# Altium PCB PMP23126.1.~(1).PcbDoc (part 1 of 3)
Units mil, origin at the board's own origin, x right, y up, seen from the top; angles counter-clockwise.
Board outline 1315.03 x 1390.8 mil, 6 copper layers (Top Layer, MidLayer1, MidLayer2, MidLayer3, MidLayer4, Bottom Layer), stack 78 mil thick; 49 components, 55 nets, 222 pads, 193 vias.
Unrouted connection lines stored in the file: 15.
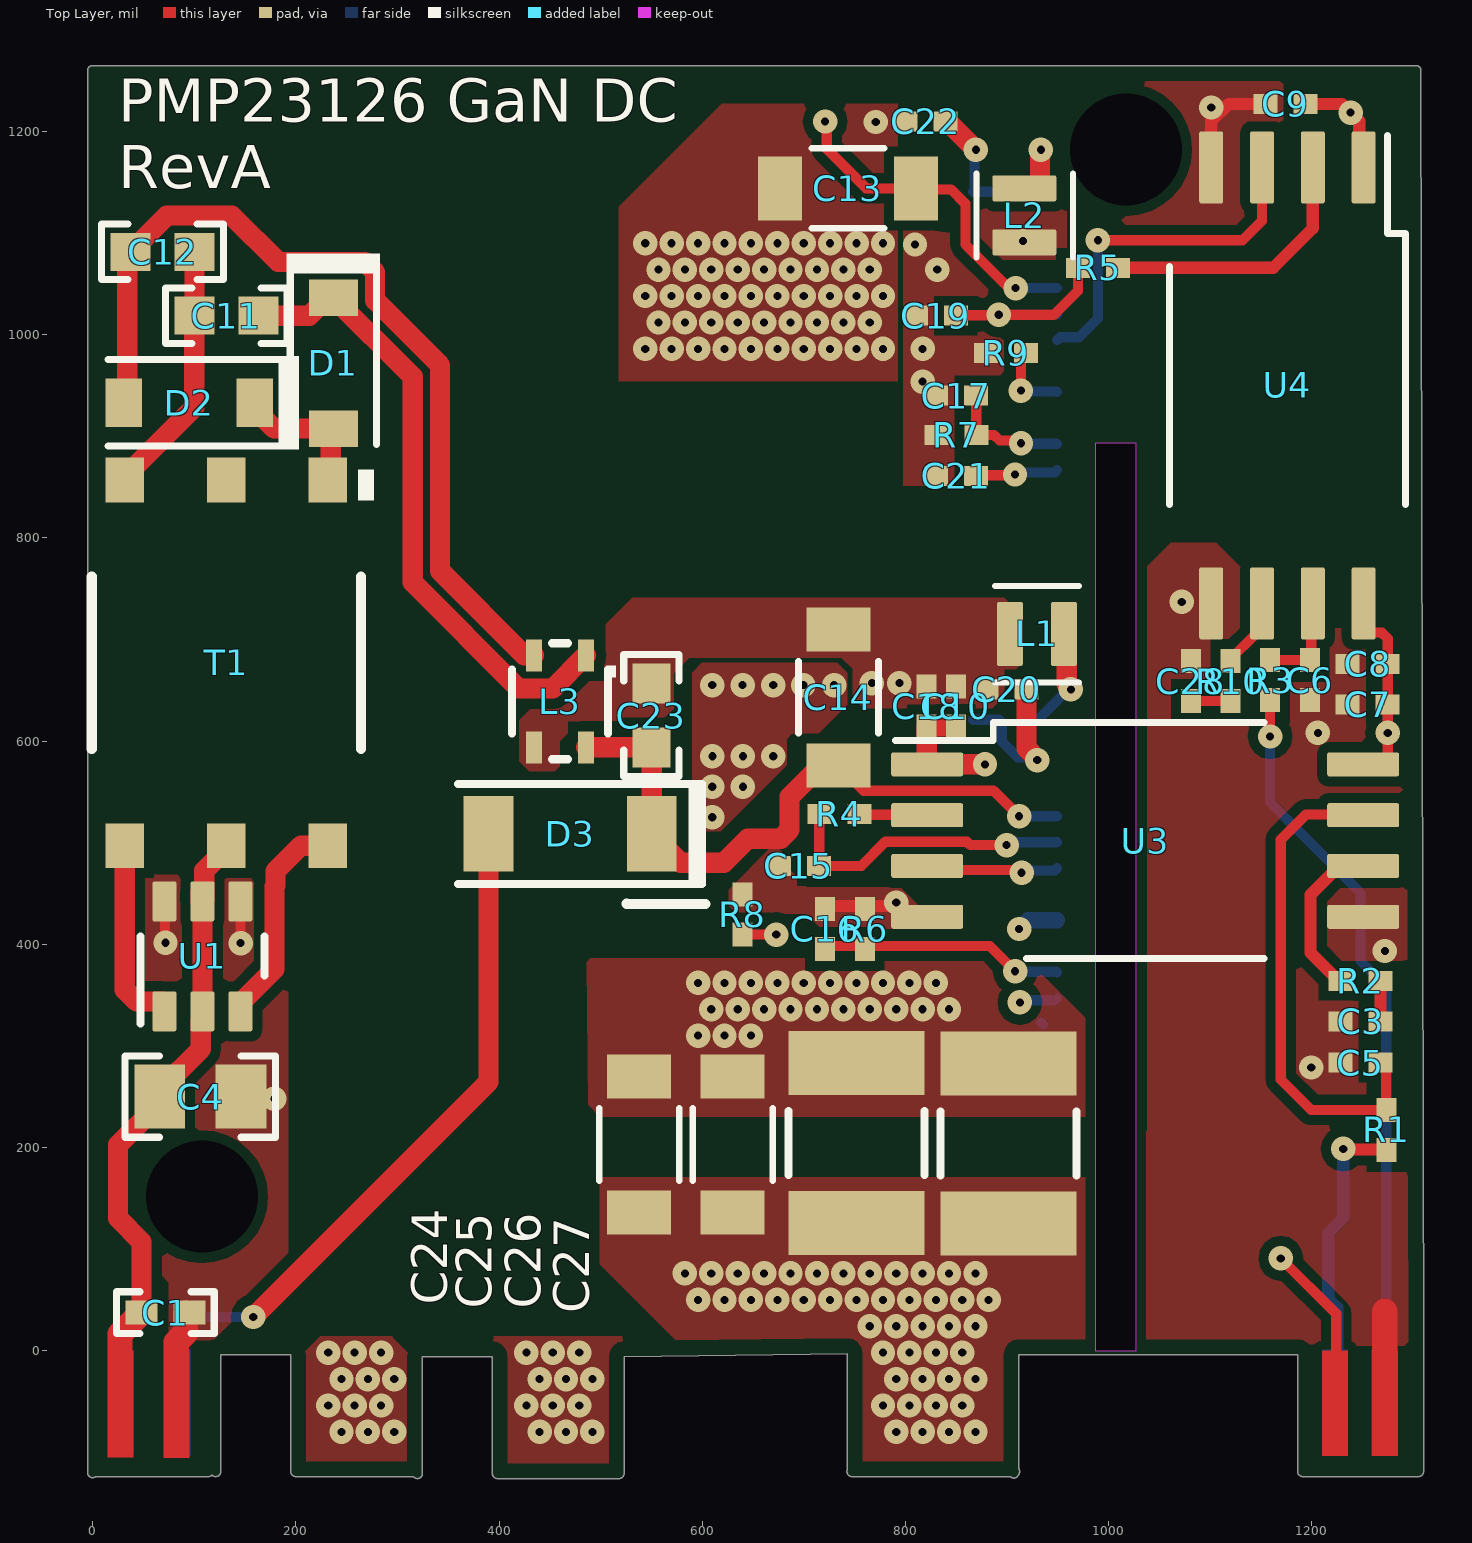
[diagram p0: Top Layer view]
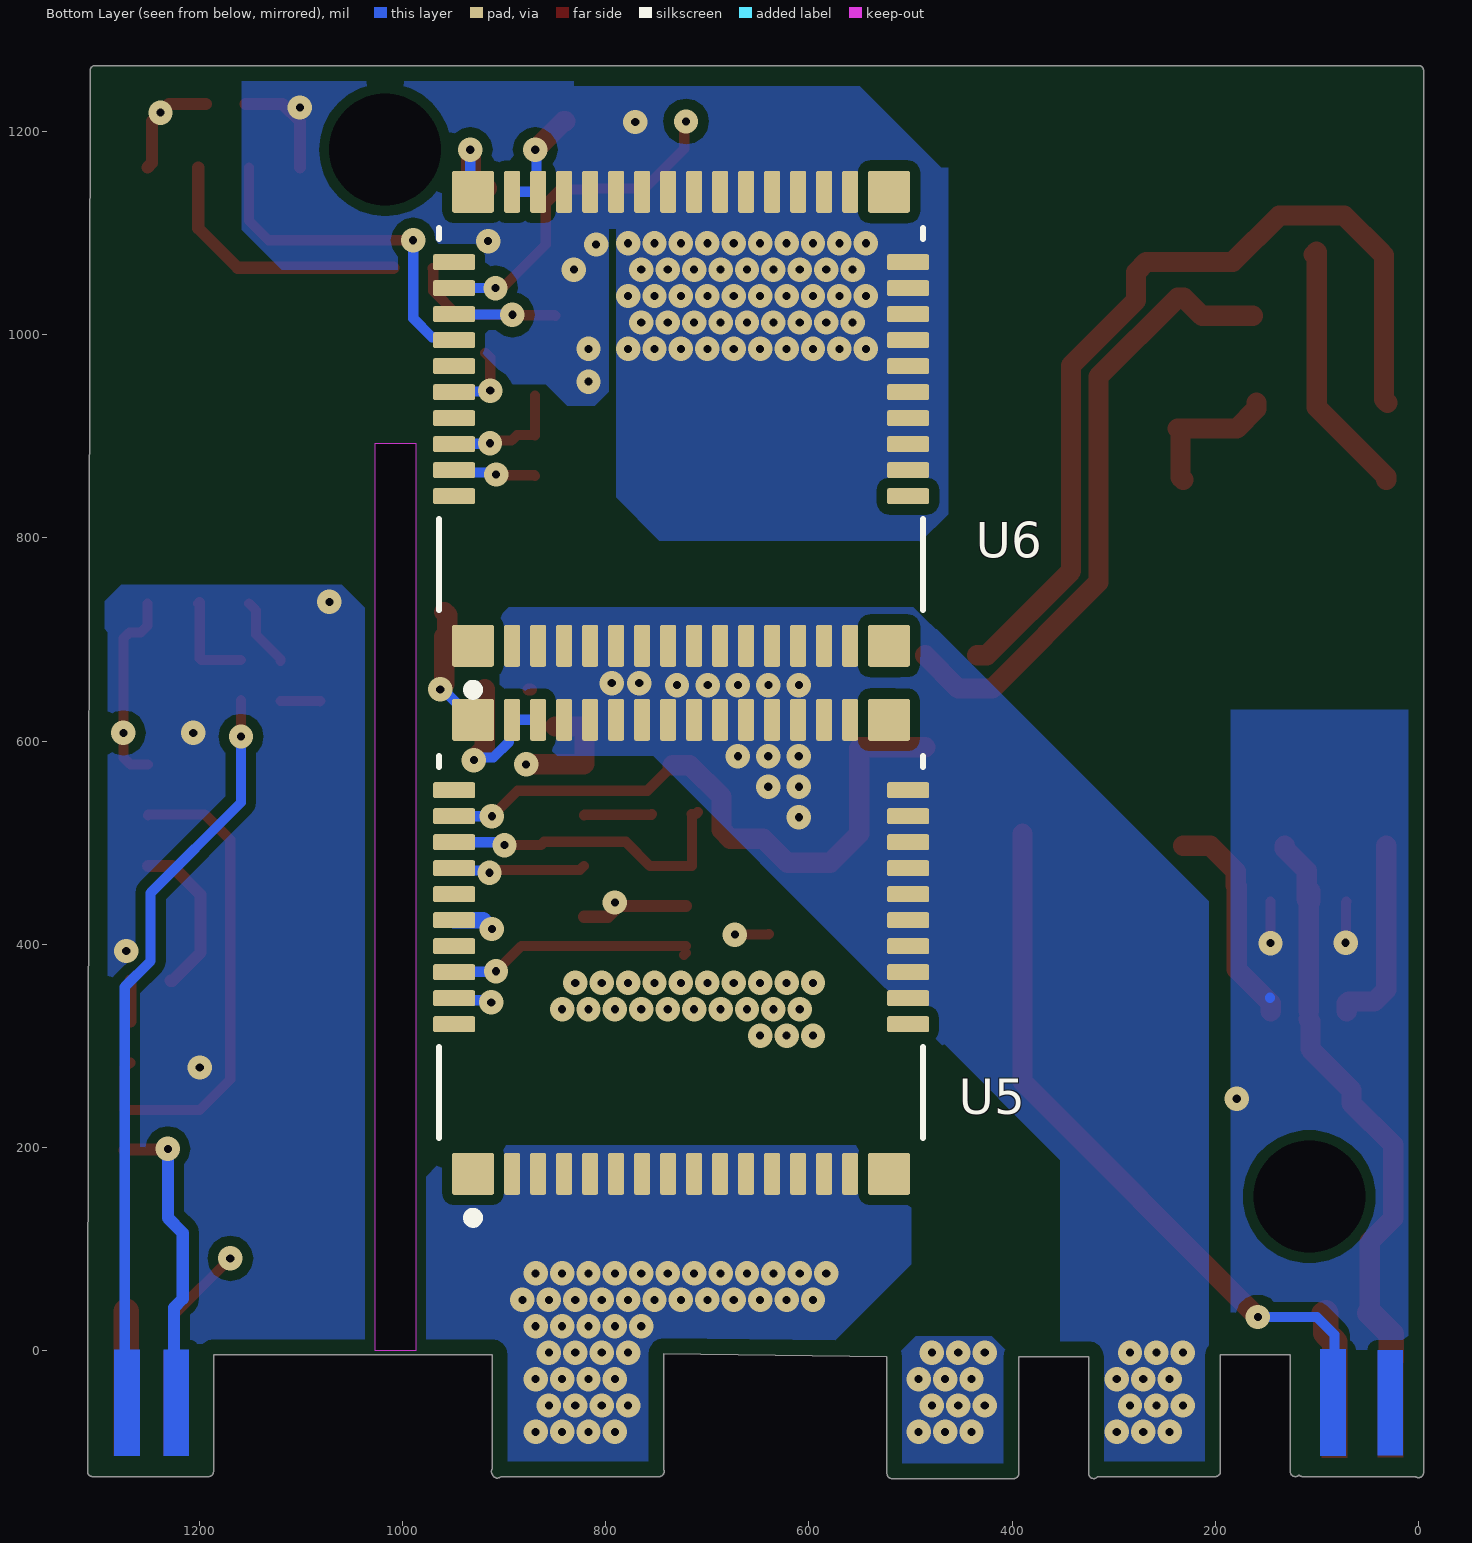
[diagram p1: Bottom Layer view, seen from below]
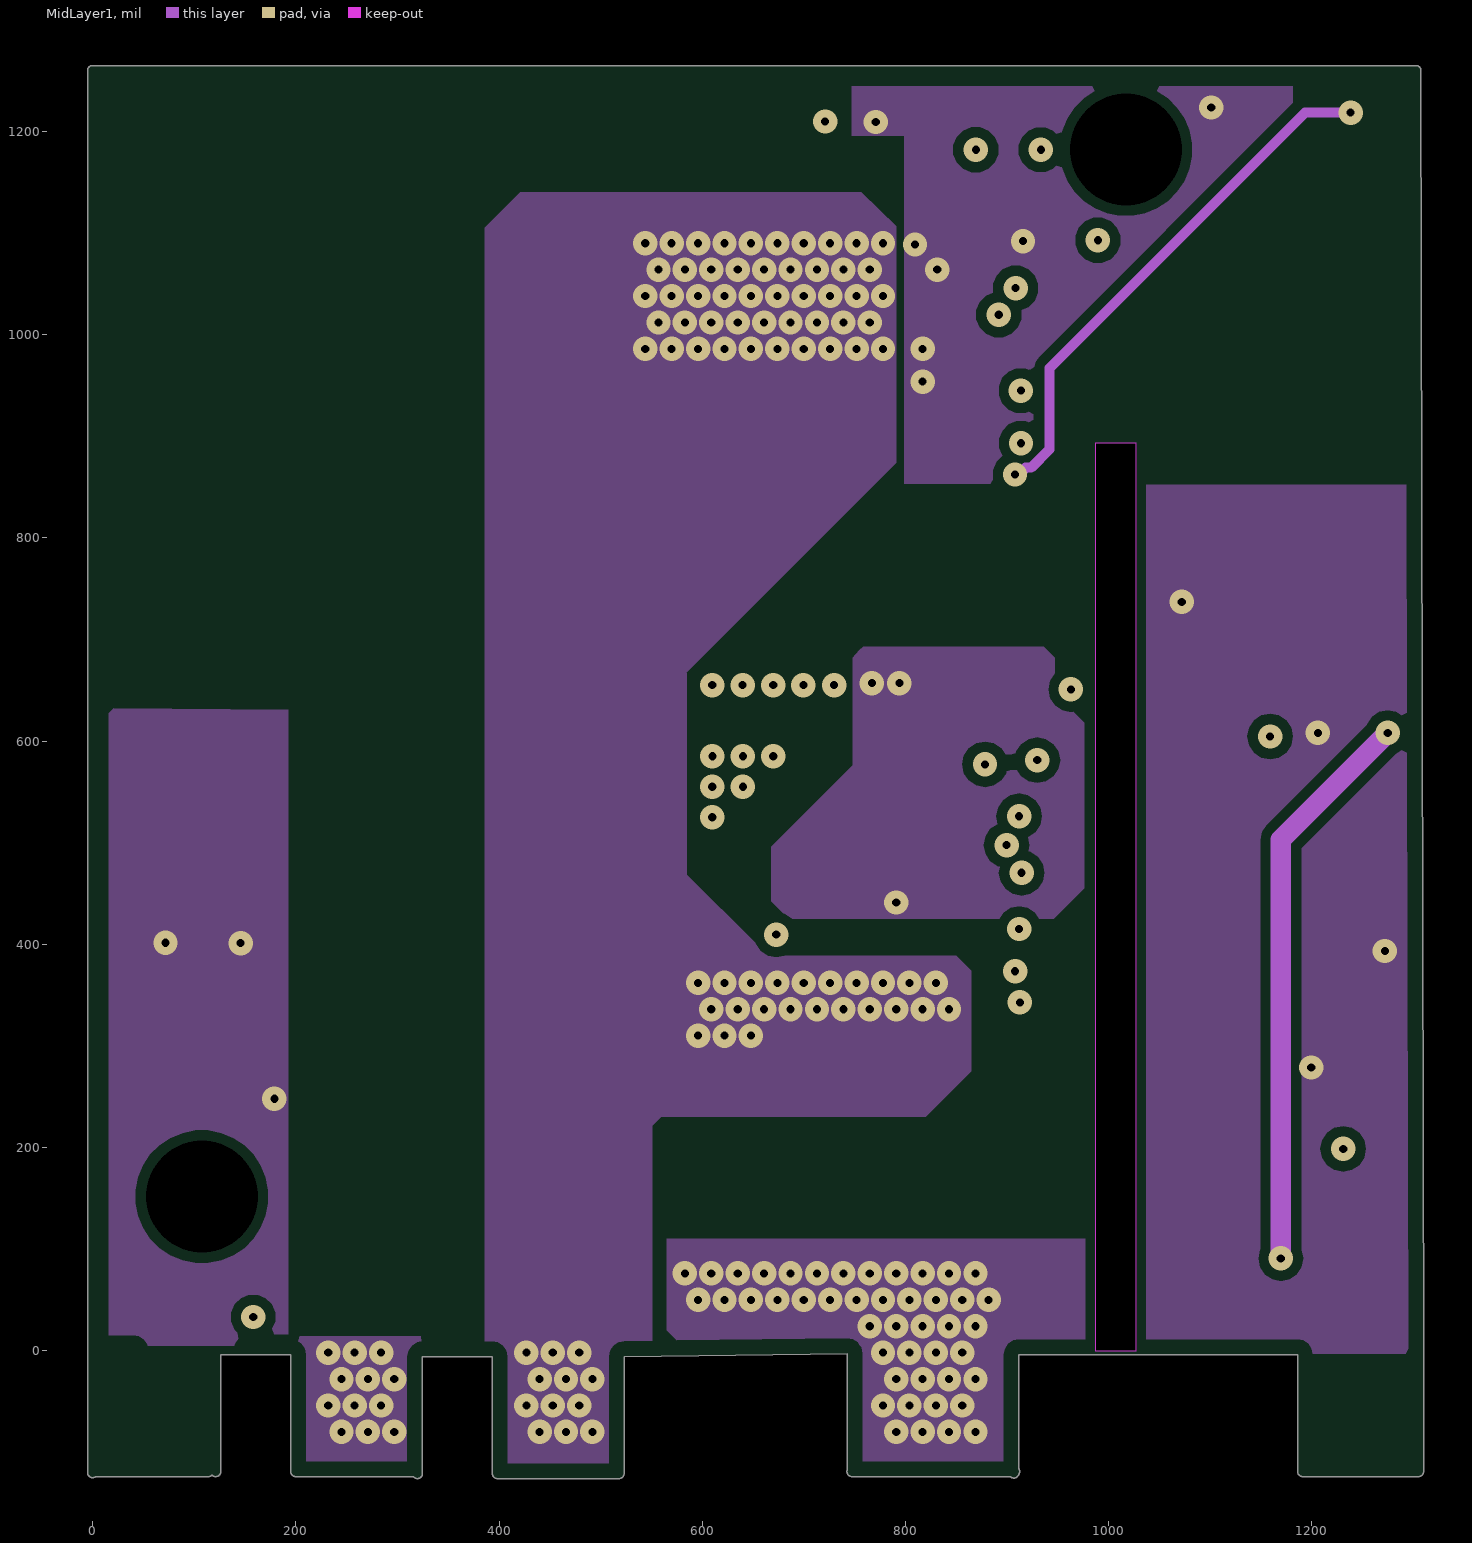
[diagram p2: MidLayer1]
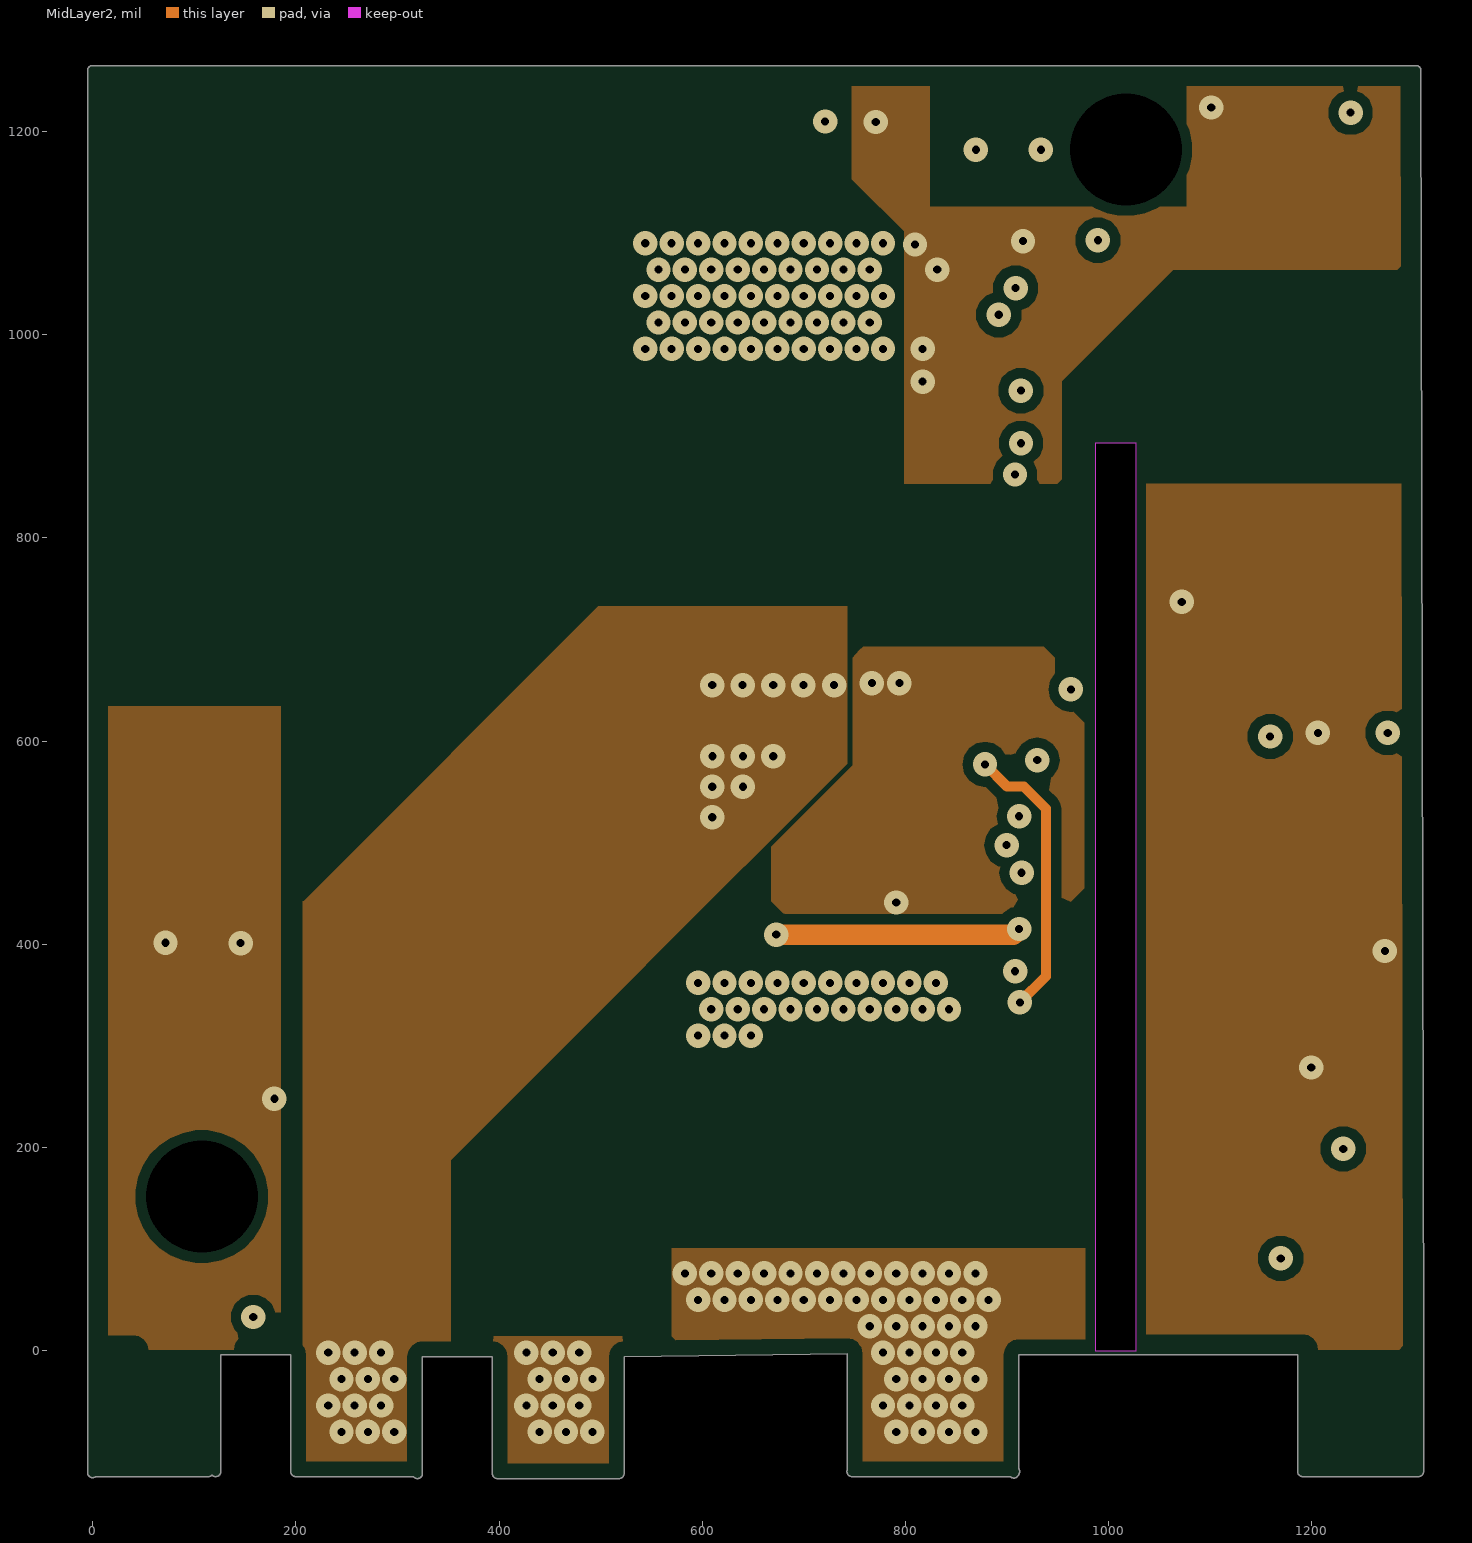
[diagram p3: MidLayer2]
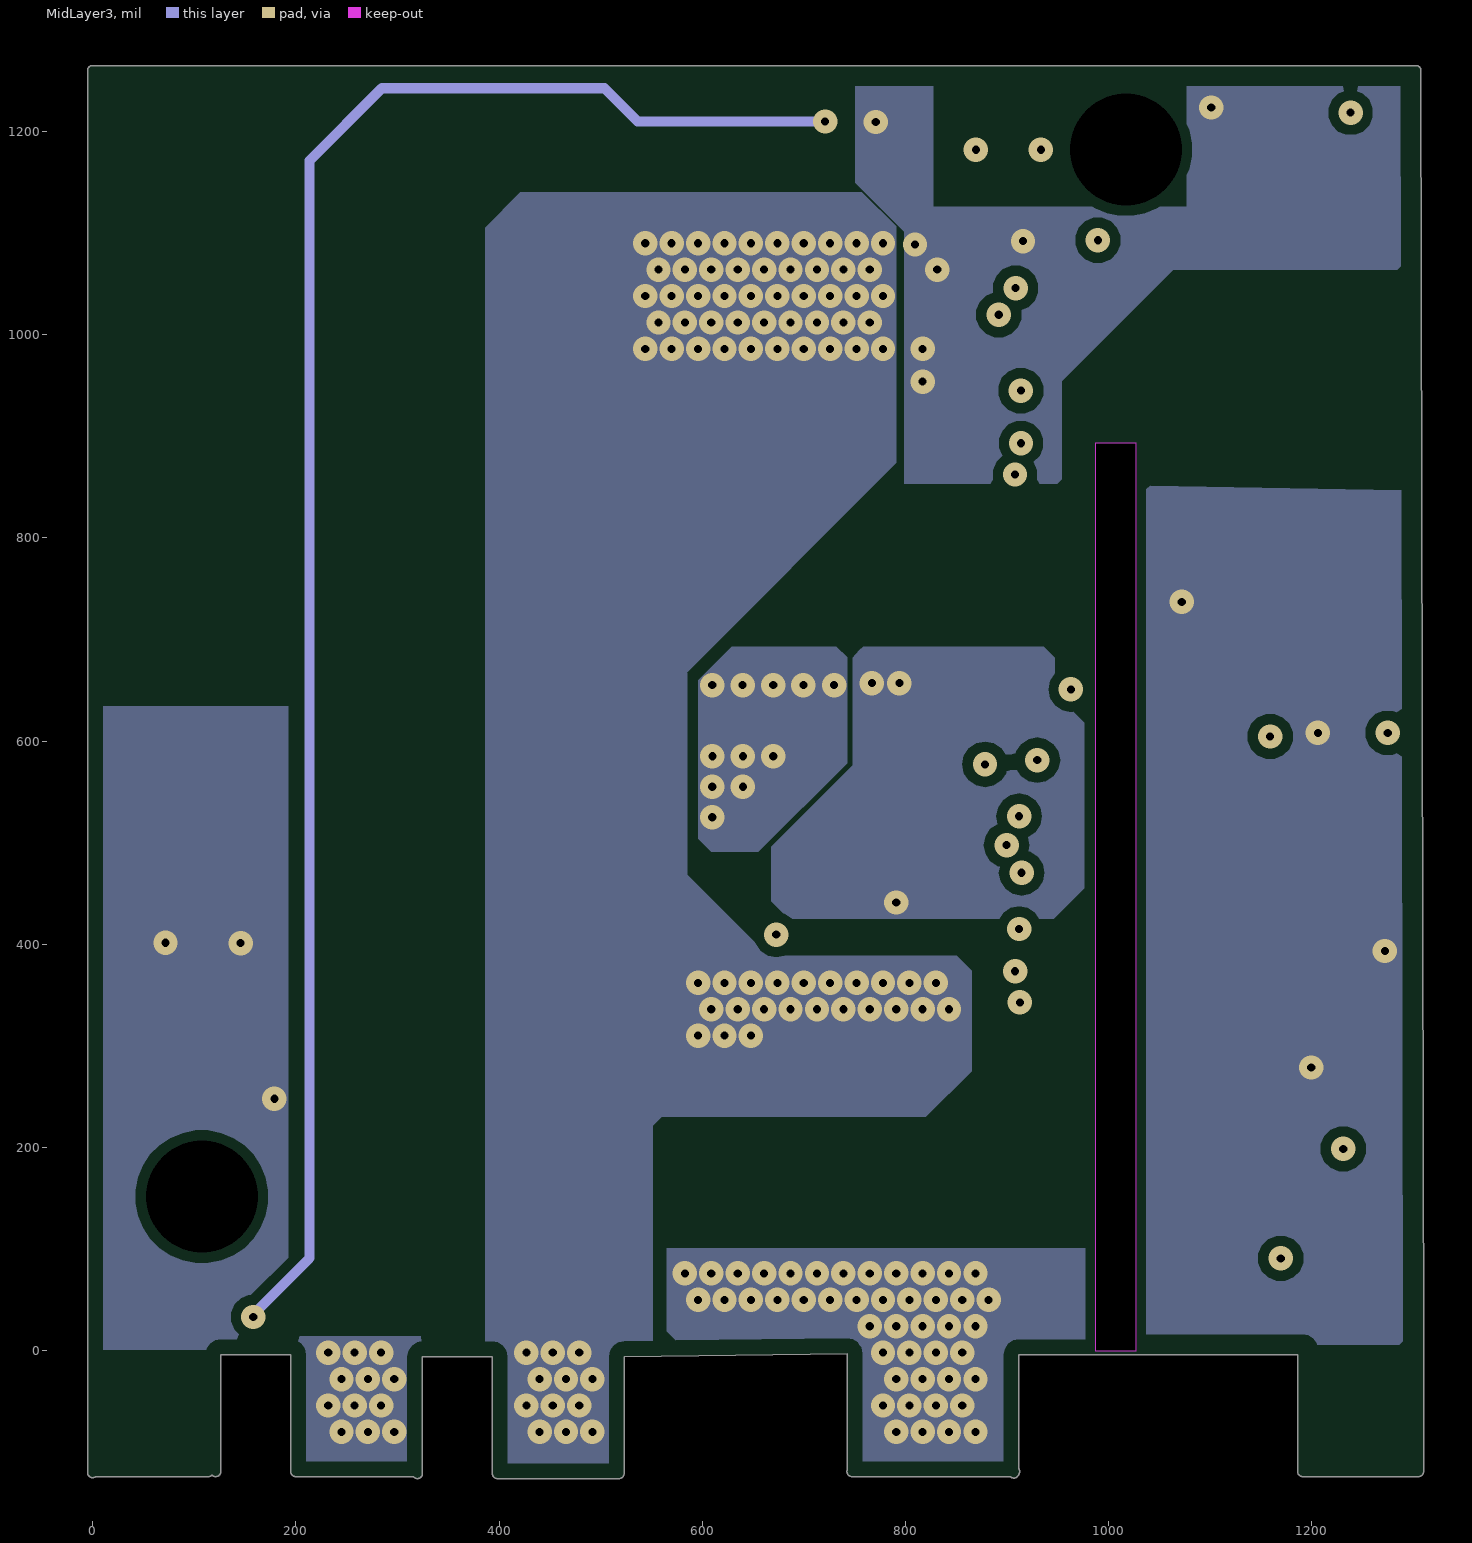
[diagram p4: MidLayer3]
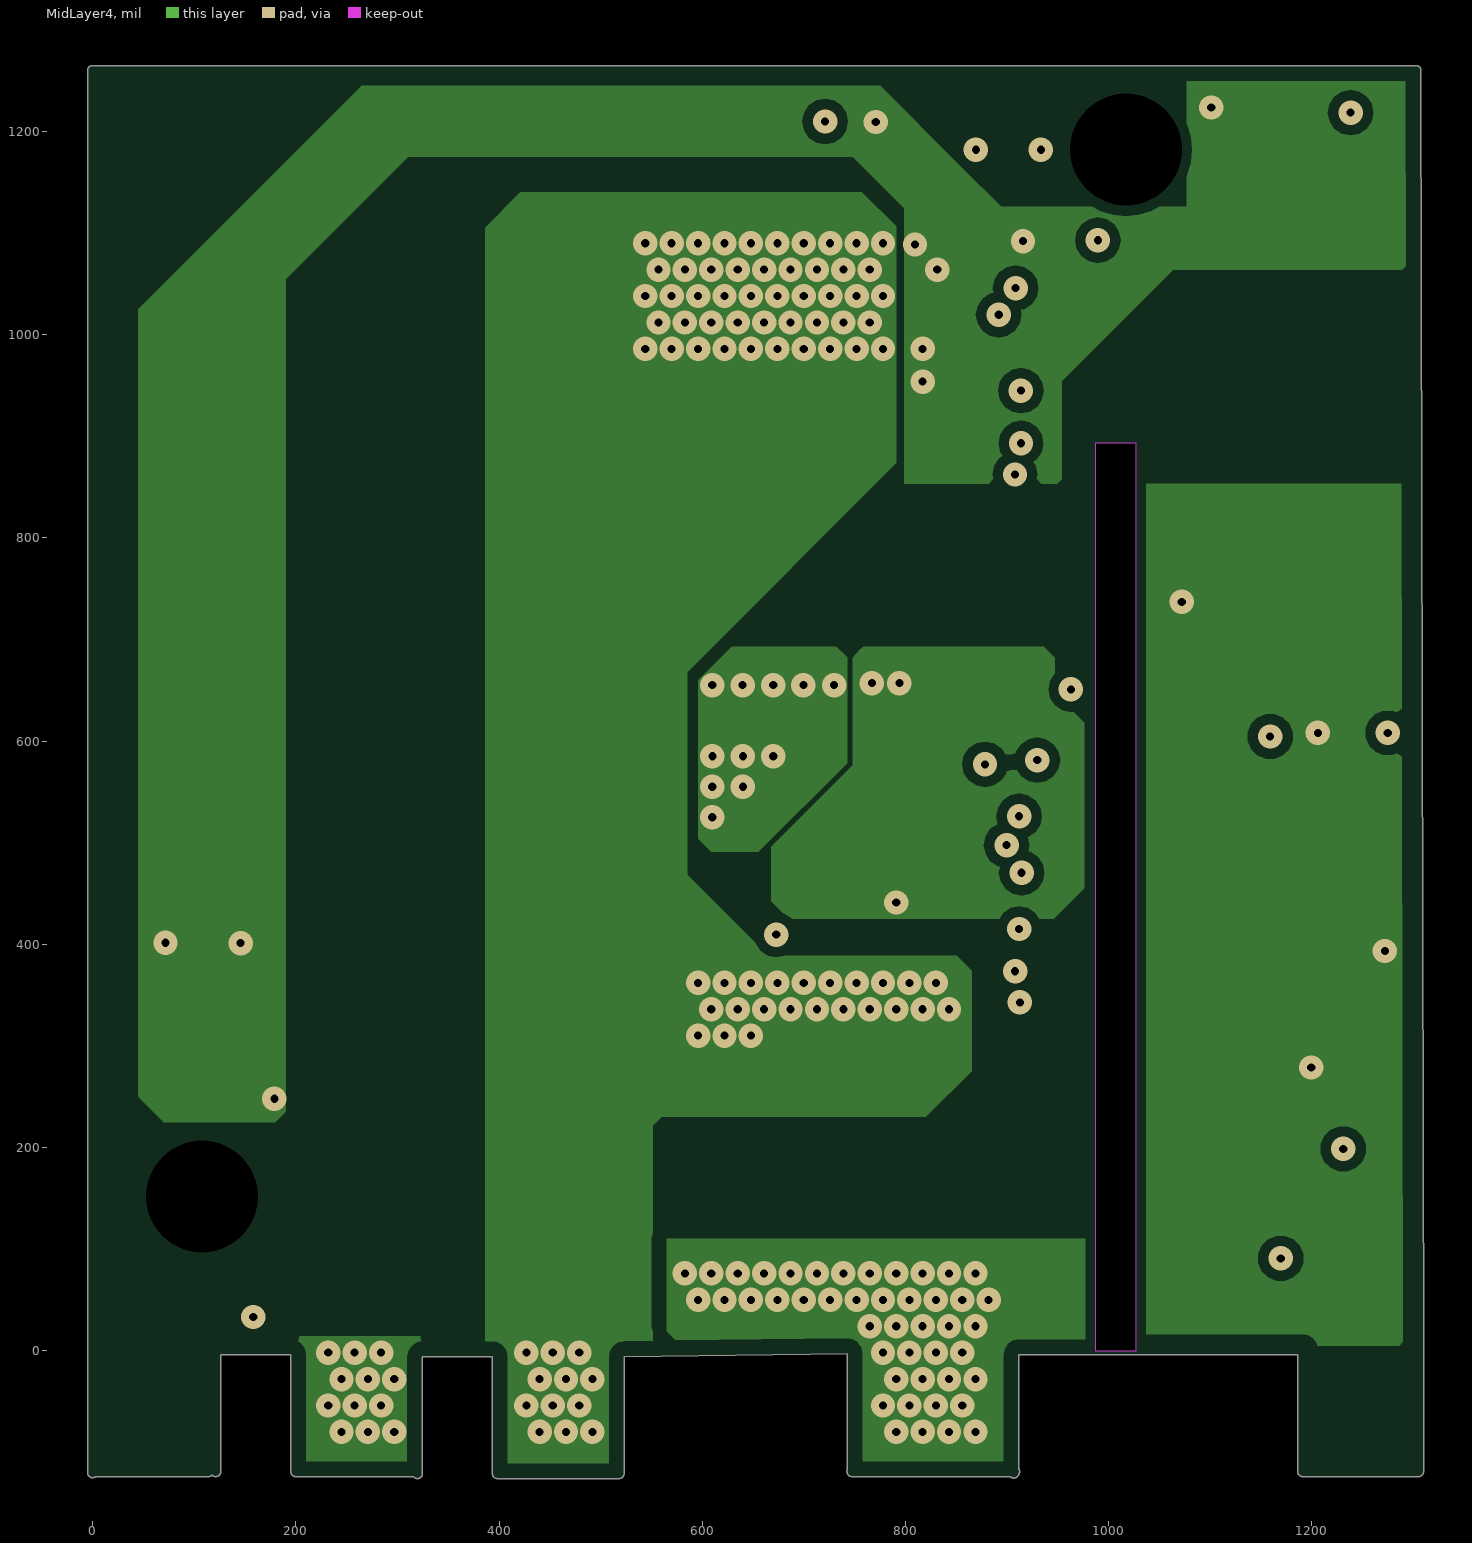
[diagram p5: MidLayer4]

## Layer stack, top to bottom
Top Solder: solder mask 0.4, Solder Resist, Dk 3.5
Top Layer: signal copper 2.8
Dielectric 1: prepreg 4.6, FR-4 High Tg, Dk 4.2
MidLayer1: signal copper 2.8
Dielectric 2: core 23.7, FR-4 High Tg, Dk 4.2
MidLayer2: signal copper 2.8
Dielectric 3: prepreg 4.6, Dk 4.2
MidLayer3: signal copper 2.8
Dielectric 4: core 23.7, Dk 4.2
MidLayer4: signal copper 2.8
Dielectric 5: prepreg 4.6, FR-4 High Tg, Dk 4.2
Bottom Layer: signal copper 2.8
Bottom Solder: solder mask 0.4, Solder Resist, Dk 3.5

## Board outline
3,-124.01 114,-124.01 ccw(c114,-119) 117.6,-122.5 ccw(c121.19,-119) 126.21,-119 126.21,-4.01 194.92,-4.01 194.92,-119 ccw(c199.93,-119) 199.93,-124.01 315.72,-124.01 ccw(c319.67,-120.93) 324.69,-120.93 324.69,-5.95 393.4,-5.95 393.4,-120.93 ccw(c398.41,-120.93) 398.41,-125.95 518.15,-125.95 ccw(c518.15,-120.93) 523.17,-120.93 523.17,-5.88 742.79,-2.93 742.79,-117.12 ccw(c747.44,-119) 747.44,-124.01 903.2,-124.01 ccw(c906.71,-120.43) 911.49,-121.96 ccw(c907.44,-119) 912.46,-119 ccw(c907.44,-119) 911.73,-116.4 911.73,-4.01 1185.99,-4.01 1185.99,-119 ccw(c1191,-119) 1191,-124.01 1305,-124.01 ccw(c1305,-119) 1310.01,-119 1310.01,1 1307.46,1259.85 ccw(c1302.44,1259.84) 1302.44,1264.86 0,1264.86 ccw(c0,1259.84) -5.01,1259.84 -5.01,-120 ccw(c0,-120)
cut-out: 1027,0 1027,893 987,893 987,0

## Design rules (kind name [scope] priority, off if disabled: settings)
AcuteAngle [All] p1: minimum=4.50000000000000E+0001 checktracksonly=FALSE
AssemblyTestPointUsage [All] p1: valid=2
BoardOutlineClearance BoardOutlineClearance_MountingHoles [OnCopper and InComponentClass('Mounting Holes')] p1: gap=40 ignorepadtopadclearanceinfootprint=FALSE
BoardOutlineClearance BoardOutlineClearance_Poly [OnCopper and IsPoly] p2: gap=15 ignorepadtopadclearanceinfootprint=FALSE
BoardOutlineClearance [OnCopper and Not InComponentClass('Logo') and not InComponentClass('FiducialMark') and not InRegion(1000,500,4000,800) and not InPoly] p3: gap=8 ignorepadtopadclearanceinfootprint=FALSE
Clearance Clearance_3 [InNamedPolygon('BOTTOM_LAYER_54V1_P128')] p1: gap=10 ignorepadtopadclearanceinfootprint=TRUE except(0: Arc-Hole Track-Hole SMDPad-Hole THPad-Hole Via-Hole Fill-Hole Poly-Hole Region-Hole Text-Hole)
Clearance Clearance_2 [InNetClass('AC') vs Not InNetClass('AC')] p2: gap=50 ignorepadtopadclearanceinfootprint=TRUE
Clearance Clearance_1 [InNetClass('HV') vs Not InNetClass('HV')] p3: gap=40 ignorepadtopadclearanceinfootprint=TRUE
Clearance Clearance_Keepouts [((IsTrack Or IsArc) And Not InPoly) And IsFree and IsKeepOut vs ((IsTrack Or IsArc) And Not InPoly) And IsFree and IsKeepOut] p4: gap=0 ignorepadtopadclearanceinfootprint=TRUE
Clearance Clearance_Poly [InPolygon] p5: gap=10 ignorepadtopadclearanceinfootprint=TRUE
Clearance Clearance_FiducialMark [IsKeepOut and InComponentClass('FiducialMark') vs IsPad and InComponentClass('FiducialMark')] p6: gap=0 ignorepadtopadclearanceinfootprint=FALSE
Clearance [All] p7: gap=7 ignorepadtopadclearanceinfootprint=FALSE
ComponentClearance ComponentClearance_MountingHoles_FiducialMarks [InComponentClass('Mounting Holes') vs InComponentClass('FiducialMark')] p1: gap=50 collisioncheckmode=3 verticalgap=10 showdistances=FALSE
ComponentClearance ComponentClearance_Shunt [InComponentClass('Header') vs InComponentClass('Shunt')] p2: gap=0 collisioncheckmode=3 verticalgap=0 showdistances=FALSE
ComponentClearance ComponentClearance_Logo [InComponentClass('Logo')] p3: gap=10 collisioncheckmode=3 verticalgap=10 showdistances=FALSE
ComponentClearance ComponentClearance_ScrewToNut [(HasFootprint('NY PMS 440 0025 PH')) vs (HasFootprint('Keystone_1902C'))] p4: gap=5 collisioncheckmode=3 verticalgap=10 showdistances=FALSE
ComponentClearance ComponentClearance_MountingHoles [InComponentClass('Mounting Holes')] p5: gap=50 collisioncheckmode=3 verticalgap=100000 showdistances=FALSE
ComponentClearance ComponentClearance_SmallPassives [HasFootprint('0201*') or HasFootprint('0402*') or HasFootprint('0508') or HasFootprint('0603*') or HasFootprint('0612') or HasFootprint('0805*') or HasFootprint('0815*') or HasFootprint('0830*') or HasFootprint('1206*') or HasFootprint('1210*') or HasFootprint('1808*') or HasFootprint('1812*') or HasFootprint('1825*') or HasFootprint('2010*') or HasFootprint('2220*') or HasFootprint('2225*') or HasFootprint('2512*') or HasFootprint('2728*') or HasFootprint('3518*') vs HasFootprint('0201*') or HasFootprint('0402*') or HasFootprint('0508') or HasFootprint('0603*') or HasFootprint('0612') or HasFootprint('0805*') or HasFootprint('0815*') or HasFootprint('0830*') or HasFootprint('1206*') or HasFootprint('1210*') or HasFootprint('1808*') or HasFootprint('1812*') or HasFootprint('1825*') or HasFootprint('2010*') or HasFootprint('2220*') or HasFootprint('2225*') or HasFootprint('2512*') or HasFootprint('2728*') or HasFootprint('3518*')] p6: gap=14.96 collisioncheckmode=3 verticalgap=10 showdistances=FALSE
ComponentClearance ComponentClearance_THtoSMT [IsThruComponent vs IsSMTComponent] p7: gap=10 collisioncheckmode=3 verticalgap=10 showdistances=FALSE
ComponentClearance ComponentClearance_THtoTH [IsThruComponent vs IsThruComponent] p8: gap=10 collisioncheckmode=3 verticalgap=10 showdistances=FALSE
ComponentClearance [All] p9: gap=10 collisioncheckmode=3 verticalgap=10 showdistances=FALSE
DiffPairsRouting [All] p1: maxlimit=100 minlimit=10 mostfreqgap=10 toplayer_minwidth=15 toplayer_maxwidth=15 toplayer_prefwidth=15 midlayer1_minwidth=15 midlayer1_maxwidth=15 midlayer1_prefwidth=15 midlayer2_minwidth=15 midlayer2_maxwidth=15 midlayer2_prefwidth=15 midlayer3_minwidth=15 midlayer3_maxwidth=15 midlayer3_prefwidth=15 midlayer4_minwidth=15 midlayer4_maxwidth=15 midlayer4_prefwidth=15 bottomlayer_minwidth=15 bottomlayer_maxwidth=15 bottomlayer_prefwidth=15 maxuncoupledlength=1000
FabricationTestPointUsage TestPointUsage [All] p1: valid=2 allowmultiple=FALSE
FabricationTestpoint Testpoint [All] p1: side=3 testpointundercomponent=TRUE minsize=40 maxsize=100 preferedsize=60 minholesize=0 maxholesize=40 preferedholesize=32 testpointgrid=1 allowsidetop=TRUE allowsidebottom=TRUE usegrid=TRUE gridtolerance=0.01
FanoutControl Fanout_LCC [IsLCC] p1: bgadir=Out bgaviamode=Centered fanoutstyle=Auto fanoutdirection=Alternating viagrid=1 // Fanout_LCC (Default Rule)
FanoutControl Fanout_BGA [IsBGA] p2: bgadir=Out bgaviamode=Centered fanoutstyle=Auto fanoutdirection=Alternating viagrid=1 // Fanout_BGA (Default Rule)
FanoutControl Fanout_Default [All] p4: bgadir=Out bgaviamode=Centered fanoutstyle=Auto fanoutdirection=Alternating viagrid=1 // Fanout_Default (Default Rule)
FanoutControl Fanout_Small [(CompPinCount < 5)] p5: bgadir=Out bgaviamode=Centered fanoutstyle=Auto fanoutdirection=OutThenIn viagrid=1 // Fanout_Small (Default Rule)
Height [All] p1: minheight=0 maxheight=1500 prefheight=500
HoleSize [All] p1: absolutevalues=TRUE maxlimit=500 minlimit=7.87 maxpercent=80.000 minpercent=20.000
HoleToHoleClearance [All] p1: gap=0 allowstackedmicrovias=TRUE
MinimumAnnularRing MinimumAnnularRing_ThermalPadVias [IsVia and InAnyComponent] p1: minimumring=5.91
MinimumAnnularRing [All] p2: minimumring=4.5
MinimumSolderMaskSliver MinimumSolderMaskSliver_Logo [InComponentClass('Logo') vs InComponentClass('Logo')] p1: minsoldermaskwidth=0.1
MinimumSolderMaskSliver [All] p2: minsoldermaskwidth=1
PlaneConnect [All] p1: planeconnectstyle=Relief reliefexpansion=10 reliefentries=4 reliefconductorwidth=10 reliefairgap=10
PolygonConnect PolygonConnect_59 [All vs IsNamedPolygon('PGND') Or  IsNamedPolygon('C102_1') Or  IsNamedPolygon('PGND') Or  IsNamedPolygon('F150_2') Or  IsNamedPolygon('C102_1') Or  IsNamedPolygon('F150_1') Or  IsNamedPolygon('C105_2') Or  IsNamedPolygon('ZCD') Or  IsNamedPolygon('C102_1') Or  IsNamedPolygon('C102_1') Or  IsNamedPolygon('PGND') Or  IsNamedPolygon('PGND') Or  IsNamedPolygon('Line') Or  IsNamedPolygon('F150_1') Or  IsNamedPolygon('ZCD') Or  IsNamedPolygon('Line') Or  IsNamedPolygon('Neutral') Or  IsNamedPolygon('F150_2') Or  IsNamedPolygon('Line') Or  IsNamedPolygon('Neutral') Or  IsNamedPolygon('F150_1') Or  IsNamedPolygon('PGND') Or  IsNamedPolygon('SWNODE') Or  IsNamedPolygon('SWNODE') Or  IsNamedPolygon('SWNODE') Or  IsNamedPolygon('PGND') Or  IsNamedPolygon('Line') Or  IsNamedPolygon('Vbulk1') Or  IsNamedPolygon('C105_2') Or  IsNamedPolygon('PGND') Or  IsNamedPolygon('C105_2') Or  IsNamedPolygon('PGND') Or  IsNamedPolygon('C105_1') Or  IsNamedPolygon('PGND') Or  IsNamedPolygon('Vbulk') Or  IsNamedPolygon('Vbulk') Or  IsNamedPolygon('F150_1') Or  IsNamedPolygon('Vbulk') Or  IsNamedPolygon('PGND') Or  IsNamedPolygon('C105_1') Or  IsNamedPolygon('Neutral') Or  IsNamedPolygon('Neutral') Or  IsNamedPolygon('SWNODE') Or  IsNamedPolygon('C102_1') Or  IsNamedPolygon('F150_2') Or  IsNamedPolygon('C105_1') Or  IsNamedPolygon('Line') Or  IsNamedPolygon('F150_2') Or  IsNamedPolygon('F150_2') Or  IsNamedPolygon('F150_1') Or  IsNamedPolygon('C105_1') Or  IsNamedPolygon('Vbulk1') Or  IsNamedPolygon('PGND') Or  IsNamedPolygon('C105_2') Or  IsNamedPolygon('F150_1') Or  IsNamedPolygon('C105_1') Or  IsNamedPolygon('F150_2') Or  IsNamedPolygon('C102_1') Or  IsNamedPolygon('PGND') Or  IsNamedPolygon('VBB') Or  IsNamedPolygon('12Vp') Or  IsNamedPolygon('J102_1') Or  IsNamedPolygon('J102_1') Or  IsNamedPolygon('Neutral') Or  IsNamedPolygon('Neutral') Or  IsNamedPolygon('PGND') Or  IsNamedPolygon('VBB') Or  IsNamedPolygon('Vbulk') Or  IsNamedPolygon('VBB') Or  IsNamedPolygon('C105_2') Or  IsNamedPolygon('ZCD') Or  IsNamedPolygon('C105_2') Or  IsNamedPolygon('ZCD') Or  IsNamedPolygon('Vbulk') Or  IsNamedPolygon('ZCD') Or  IsNamedPolygon('5Vp') Or  IsNamedPolygon('J102_1') Or  IsNamedPolygon('SWNODE') Or  IsNamedPolygon('PGND') Or  IsNamedPolygon('ZCD') Or  IsNamedPolygon('D106_1') Or  IsNamedPolygon('VBB') Or  IsNamedPolygon('J102_1') Or  IsNamedPolygon('J102_1') Or  IsNamedPolygon('PGND') Or  IsNamedPolygon('VBB') Or  IsNamedPolygon('D106_1') Or  IsNamedPolygon('PGND') Or  IsNamedPolygon('SWNODE') Or  IsNamedPolygon('ZCD') Or  IsNamedPolygon('PGND') Or  IsNamedPolygon('Vbulk1') Or  IsNamedPolygon('ZCD') Or  IsNamedPolygon('Line') Or  IsNamedPolygon('Vbulk') Or  IsNamedPolygon('PGND') Or  IsNamedPolygon('PGND') Or  IsNamedPolygon('VBB') Or  IsNamedPolygon('PGND') Or  IsNamedPolygon('C105_1') Or  IsNamedPolygon('VBB') Or  IsNamedPolygon('ZCD') Or  IsNamedPolygon('Neutral') Or  IsNamedPolygon('ZCD') Or  IsNamedPolygon('PE') Or  IsNamedPolygon('J102_1') Or  IsNamedPolygon('Vbulk') Or  IsNamedPolygon('Vbulk1')] p1: connectstyle=Direct reliefconductorwidth=10 reliefentries=4 polygonreliefangle="90 Angle" airgapwidth=10
PolygonConnect PolygonConnect_58 [All vs IsNamedPolygon('C105_1') Or  IsNamedPolygon('12Vp') Or  IsNamedPolygon('Neutral') Or  IsNamedPolygon('C105_2') Or  IsNamedPolygon('ZCD') Or  IsNamedPolygon('C105_1') Or  IsNamedPolygon('VBB') Or  IsNamedPolygon('PGND') Or  IsNamedPolygon('F150_2') Or  IsNamedPolygon('SWNODE') Or  IsNamedPolygon('PGND') Or  IsNamedPolygon('PGND') Or  IsNamedPolygon('J102_1') Or  IsNamedPolygon('D106_1') Or  IsNamedPolygon('PGND') Or  IsNamedPolygon('C105_2') Or  IsNamedPolygon('SWNODE') Or  IsNamedPolygon('Vbulk') Or  IsNamedPolygon('PGND') Or  IsNamedPolygon('PGND') Or  IsNamedPolygon('PGND') Or  IsNamedPolygon('PGND') Or  IsNamedPolygon('Vbulk') Or  IsNamedPolygon('PGND') Or  IsNamedPolygon('PGND') Or  IsNamedPolygon('D106_1') Or  IsNamedPolygon('Neutral') Or  IsNamedPolygon('PGND') Or  IsNamedPolygon('C105_2') Or  IsNamedPolygon('Vbulk') Or  IsNamedPolygon('SWNODE') Or  IsNamedPolygon('VBB') Or  IsNamedPolygon('J102_1') Or  IsNamedPolygon('VBB') Or  IsNamedPolygon('PGND') Or  IsNamedPolygon('5Vp') Or  IsNamedPolygon('SWNODE') Or  IsNamedPolygon('C105_1') Or  IsNamedPolygon('VBB') Or  IsNamedPolygon('SWNODE') Or  IsNamedPolygon('ZCD') Or  IsNamedPolygon('Vbulk') Or  IsNamedPolygon('Line') Or  IsNamedPolygon('Vbulk1') Or  IsNamedPolygon('PGND') Or  IsNamedPolygon('ZCD') Or  IsNamedPolygon('VBB') Or  IsNamedPolygon('PGND') Or  IsNamedPolygon('ZCD') Or  IsNamedPolygon('Vbulk1') Or  IsNamedPolygon('Neutral') Or  IsNamedPolygon('F150_2') Or  IsNamedPolygon('F150_2') Or  IsNamedPolygon('PGND') Or  IsNamedPolygon('Neutral') Or  IsNamedPolygon('C102_1') Or  IsNamedPolygon('C105_1') Or  IsNamedPolygon('Line') Or  IsNamedPolygon('J102_1') Or  IsNamedPolygon('Neutral') Or  IsNamedPolygon('Neutral') Or  IsNamedPolygon('SWNODE') Or  IsNamedPolygon('ZCD') Or  IsNamedPolygon('J102_1') Or  IsNamedPolygon('J102_1') Or  IsNamedPolygon('PGND') Or  IsNamedPolygon('ZCD') Or  IsNamedPolygon('Vbulk') Or  IsNamedPolygon('Line') Or  IsNamedPolygon('VBB') Or  IsNamedPolygon('Vbulk') Or  IsNamedPolygon('VBB') Or  IsNamedPolygon('Line') Or  IsNamedPolygon('C105_1') Or  IsNamedPolygon('ZCD') Or  IsNamedPolygon('C105_2') Or  IsNamedPolygon('Line') Or  IsNamedPolygon('C105_2') Or  IsNamedPolygon('PGND') Or  IsNamedPolygon('PE') Or  IsNamedPolygon('Neutral') Or  IsNamedPolygon('F150_2') Or  IsNamedPolygon('ZCD') Or  IsNamedPolygon('F150_2') Or  IsNamedPolygon('F150_2') Or  IsNamedPolygon('ZCD') Or  IsNamedPolygon('PGND') Or  IsNamedPolygon('PGND') Or  IsNamedPolygon('Vbulk1') Or  IsNamedPolygon('Line') Or  IsNamedPolygon('ZCD') Or  IsNamedPolygon('C105_1') Or  IsNamedPolygon('J102_1') Or  IsNamedPolygon('Vbulk1') Or  IsNamedPolygon('Vbulk') Or  IsNamedPolygon('C105_2') Or  IsNamedPolygon('PGND')] p2: connectstyle=Direct reliefconductorwidth=10 reliefentries=4 polygonreliefangle="90 Angle" airgapwidth=10
PolygonConnect PolygonConnect_57 [All vs IsNamedPolygon('PGND') Or  IsNamedPolygon('C105_2') Or  IsNamedPolygon('VBB') Or  IsNamedPolygon('5Vp') Or  IsNamedPolygon('ZCD') Or  IsNamedPolygon('J102_1') Or  IsNamedPolygon('PGND') Or  IsNamedPolygon('PGND') Or  IsNamedPolygon('PGND') Or  IsNamedPolygon('PE') Or  IsNamedPolygon('VBB') Or  IsNamedPolygon('VBB') Or  IsNamedPolygon('ZCD') Or  IsNamedPolygon('ZCD') Or  IsNamedPolygon('Line') Or  IsNamedPolygon('PGND') Or  IsNamedPolygon('C102_1') Or  IsNamedPolygon('VBB') Or  IsNamedPolygon('J102_1') Or  IsNamedPolygon('Vbulk') Or  IsNamedPolygon('PGND') Or  IsNamedPolygon('Neutral') Or  IsNamedPolygon('Vbulk') Or  IsNamedPolygon('ZCD') Or  IsNamedPolygon('J102_1') Or  IsNamedPolygon('PGND') Or  IsNamedPolygon('ZCD') Or  IsNamedPolygon('J102_1') Or  IsNamedPolygon('VBB') Or  IsNamedPolygon('Neutral') Or  IsNamedPolygon('PGND') Or  IsNamedPolygon('PGND') Or  IsNamedPolygon('12Vp') Or  IsNamedPolygon('Vbulk') Or  IsNamedPolygon('PGND') Or  IsNamedPolygon('Vbulk') Or  IsNamedPolygon('J102_1') Or  IsNamedPolygon('PGND') Or  IsNamedPolygon('D106_1') Or  IsNamedPolygon('PGND') Or  IsNamedPolygon('Vbulk1') Or  IsNamedPolygon('PGND') Or  IsNamedPolygon('C105_2') Or  IsNamedPolygon('Vbulk') Or  IsNamedPolygon('Neutral') Or  IsNamedPolygon('Vbulk1') Or  IsNamedPolygon('PGND') Or  IsNamedPolygon('PGND') Or  IsNamedPolygon('J102_1') Or  IsNamedPolygon('SWNODE') Or  IsNamedPolygon('Vbulk1') Or  IsNamedPolygon('C105_2') Or  IsNamedPolygon('VBB') Or  IsNamedPolygon('VBB') Or  IsNamedPolygon('ZCD') Or  IsNamedPolygon('SWNODE') Or  IsNamedPolygon('Vbulk') Or  IsNamedPolygon('PGND') Or  IsNamedPolygon('Vbulk') Or  IsNamedPolygon('C105_1') Or  IsNamedPolygon('PGND') Or  IsNamedPolygon('PGND') Or  IsNamedPolygon('ZCD') Or  IsNamedPolygon('C105_2') Or  IsNamedPolygon('D106_1') Or  IsNamedPolygon('PGND') Or  IsNamedPolygon('C105_2') Or  IsNamedPolygon('C105_2') Or  IsNamedPolygon('ZCD') Or  IsNamedPolygon('PGND')] p3: connectstyle=Direct reliefconductorwidth=10 reliefentries=4 polygonreliefangle="90 Angle" airgapwidth=10
PolygonConnect PolygonConnect_56 [All vs IsNamedPolygon('PGND') Or  IsNamedPolygon('C105_2') Or  IsNamedPolygon('VBB') Or  IsNamedPolygon('5Vp') Or  IsNamedPolygon('ZCD') Or  IsNamedPolygon('J102_1') Or  IsNamedPolygon('PGND') Or  IsNamedPolygon('PGND') Or  IsNamedPolygon('PGND') Or  IsNamedPolygon('PE') Or  IsNamedPolygon('VBB') Or  IsNamedPolygon('VBB') Or  IsNamedPolygon('ZCD') Or  IsNamedPolygon('ZCD') Or  IsNamedPolygon('Line') Or  IsNamedPolygon('PGND') Or  IsNamedPolygon('C102_1') Or  IsNamedPolygon('VBB') Or  IsNamedPolygon('J102_1') Or  IsNamedPolygon('Vbulk') Or  IsNamedPolygon('PGND') Or  IsNamedPolygon('Neutral') Or  IsNamedPolygon('Vbulk') Or  IsNamedPolygon('ZCD') Or  IsNamedPolygon('J102_1') Or  IsNamedPolygon('PGND') Or  IsNamedPolygon('ZCD') Or  IsNamedPolygon('J102_1') Or  IsNamedPolygon('VBB') Or  IsNamedPolygon('Neutral') Or  IsNamedPolygon('PGND') Or  IsNamedPolygon('PGND') Or  IsNamedPolygon('12Vp') Or  IsNamedPolygon('Vbulk') Or  IsNamedPolygon('PGND') Or  IsNamedPolygon('Vbulk') Or  IsNamedPolygon('J102_1') Or  IsNamedPolygon('PGND') Or  IsNamedPolygon('D106_1') Or  IsNamedPolygon('PGND') Or  IsNamedPolygon('Vbulk1') Or  IsNamedPolygon('PGND') Or  IsNamedPolygon('C105_2') Or  IsNamedPolygon('Vbulk') Or  IsNamedPolygon('Neutral') Or  IsNamedPolygon('Vbulk1') Or  IsNamedPolygon('PGND') Or  IsNamedPolygon('PGND') Or  IsNamedPolygon('J102_1') Or  IsNamedPolygon('SWNODE') Or  IsNamedPolygon('Vbulk1') Or  IsNamedPolygon('C105_2') Or  IsNamedPolygon('VBB') Or  IsNamedPolygon('VBB') Or  IsNamedPolygon('ZCD') Or  IsNamedPolygon('SWNODE') Or  IsNamedPolygon('Vbulk') Or  IsNamedPolygon('PGND') Or  IsNamedPolygon('Vbulk') Or  IsNamedPolygon('C105_1') Or  IsNamedPolygon('PGND') Or  IsNamedPolygon('PGND') Or  IsNamedPolygon('ZCD') Or  IsNamedPolygon('C105_2') Or  IsNamedPolygon('D106_1') Or  IsNamedPolygon('PGND') Or  IsNamedPolygon('C105_2') Or  IsNamedPolygon('C105_2') Or  IsNamedPolygon('ZCD') Or  IsNamedPolygon('PGND')] p4: thpad.connectstyle=Direct thpad.reliefconductorwidth=10 thpad.reliefentries=4 thpad.polygonreliefangle="90 Angle" thpad.airgapwidth=10 smdpad.connectstyle=Relief smdpad.reliefconductorwidth=10 smdpad.reliefentries=4 smdpad.polygonreliefangle="90 Angle" smdpad.airgapwidth=10 via.connectstyle=Relief via.reliefconductorwidth=10 via.reliefentries=4 via.polygonreliefangle="90 Angle" via.airgapwidth=10
PolygonConnect PolygonConnect_55 [All vs IsNamedPolygon('SWNODE') Or  IsNamedPolygon('ZCD') Or  IsNamedPolygon('PGND') Or  IsNamedPolygon('PGND') Or  IsNamedPolygon('PGND') Or  IsNamedPolygon('PGND') Or  IsNamedPolygon('PGND') Or  IsNamedPolygon('PGND') Or  IsNamedPolygon('Vbulk') Or  IsNamedPolygon('D106_1') Or  IsNamedPolygon('Vbulk') Or  IsNamedPolygon('D106_1') Or  IsNamedPolygon('VBB') Or  IsNamedPolygon('PGND') Or  IsNamedPolygon('PGND') Or  IsNamedPolygon('Vbulk') Or  IsNamedPolygon('VBB') Or  IsNamedPolygon('ZCD') Or  IsNamedPolygon('Vbulk') Or  IsNamedPolygon('ZCD') Or  IsNamedPolygon('VBB') Or  IsNamedPolygon('VBB') Or  IsNamedPolygon('VBB') Or  IsNamedPolygon('VBB') Or  IsNamedPolygon('VBB') Or  IsNamedPolygon('ZCD') Or  IsNamedPolygon('C102_1') Or  IsNamedPolygon('12Vp') Or  IsNamedPolygon('C105_1') Or  IsNamedPolygon('PGND') Or  IsNamedPolygon('SWNODE') Or  IsNamedPolygon('Vbulk') Or  IsNamedPolygon('Vbulk1') Or  IsNamedPolygon('Vbulk1') Or  IsNamedPolygon('Neutral') Or  IsNamedPolygon('ZCD') Or  IsNamedPolygon('Neutral') Or  IsNamedPolygon('ZCD') Or  IsNamedPolygon('5Vp') Or  IsNamedPolygon('Neutral') Or  IsNamedPolygon('ZCD') Or  IsNamedPolygon('Line') Or  IsNamedPolygon('ZCD')] p5: connectstyle=Direct reliefconductorwidth=10 reliefentries=4 polygonreliefangle="90 Angle" airgapwidth=10
PolygonConnect PolygonConnect_54 [All vs IsNamedPolygon('12Vp') Or  IsNamedPolygon('SWNODE') Or  IsNamedPolygon('D403_2') Or  IsNamedPolygon('D403_2') Or  IsNamedPolygon('PGND') Or  IsNamedPolygon('BOTTOM_LAYER_NETC106_2_P030') Or  IsNamedPolygon('C102_1') Or  IsNamedPolygon('SGND') Or  IsNamedPolygon('TOP_LAYER_54V1_P046') Or  IsNamedPolygon('TOP_LAYER_54V2_P048') Or  IsNamedPolygon('TOP_LAYER_54V2_P048') Or  IsNamedPolygon('C108_1') Or  IsNamedPolygon('C108_1') Or  IsNamedPolygon('C108_1') Or  IsNamedPolygon('C108_1') Or  IsNamedPolygon('C108_1') Or  IsNamedPolygon('C108_1') Or  IsNamedPolygon('PGND') Or  IsNamedPolygon('ZCD') Or  IsNamedPolygon('Line') Or  IsNamedPolygon('5Vp') Or  IsNamedPolygon('12Vp') Or  IsNamedPolygon('T200_4') Or  IsNamedPolygon('T200_6') Or  IsNamedPolygon('SWNODE3') Or  IsNamedPolygon('T200_4') Or  IsNamedPolygon('T200_6') Or  IsNamedPolygon('SWNODE4') Or  IsNamedPolygon('VSR') Or  IsNamedPolygon('TOP_LAYER_IOUT_SNS_P092') Or  IsNamedPolygon('SIGNAL_LAYER_2_VBB_P094') Or  IsNamedPolygon('Vbulk1') Or  IsNamedPolygon('TOP_LAYER_VBULK_P104') Or  IsNamedPolygon('SIGNAL_LAYER_1_VBULK1_P106') Or  IsNamedPolygon('Line') Or  IsNamedPolygon('Line') Or  IsNamedPolygon('D404_2') Or  IsNamedPolygon('Vbulk') Or  IsNamedPolygon('D400_2') Or  IsNamedPolygon('SGND') Or  IsNamedPolygon('PGND') Or  IsNamedPolygon('TOP_LAYER_12VS_P126') Or  IsNamedPolygon('LEG3_HS_DRV') Or  IsNamedPolygon('LEG4_LS_DRV') Or  IsNamedPolygon('LEG4_HS_DRV') Or  IsNamedPolygon('SWNODE4') Or  IsNamedPolygon('SWNODE3') Or  IsNamedPolygon('T200_6') Or  IsNamedPolygon('T200_4') Or  IsNamedPolygon('VBB') Or  IsNamedPolygon('5Vs') Or  IsNamedPolygon('SGND') Or  IsNamedPolygon('Iout_SNS') Or  IsNamedPolygon('SGND') Or  IsNamedPolygon('SWNODE3') Or  IsNamedPolygon('SWNODE3') Or  IsNamedPolygon('SWNODE3') Or  IsNamedPolygon('SWNODE3') Or  IsNamedPolygon('SGND') Or  IsNamedPolygon('SGND') Or  IsNamedPolygon('SGND') Or  IsNamedPolygon('SWNODE4') Or  IsNamedPolygon('SWNODE4') Or  IsNamedPolygon('SWNODE4') Or  IsNamedPolygon('VSR') Or  IsNamedPolygon('SWNODE3') Or  IsNamedPolygon('SGND') Or  IsNamedPolygon('SGND') Or  IsNamedPolygon('SGND') Or  IsNamedPolygon('SGND') Or  IsNamedPolygon('SGND') Or  IsNamedPolygon('SGND') Or  IsNamedPolygon('54V1') Or  IsNamedPolygon('SGND') Or  IsNamedPolygon('VSR') Or  IsNamedPolygon('C102_1') Or  IsNamedPolygon('C102_1') Or  IsNamedPolygon('C102_1') Or  IsNamedPolygon('C102_1') Or  IsNamedPolygon('C102_1') Or  IsNamedPolygon('ZCD') Or  IsNamedPolygon('PGND') Or  IsNamedPolygon('PGND') Or  IsNamedPolygon('Vbulk1') Or  IsNamedPolygon('Vbulk') Or  IsNamedPolygon('Vbulk1') Or  IsNamedPolygon('Vbulk1') Or  IsNamedPolygon('ZCD') Or  IsNamedPolygon('Neutral') Or  IsNamedPolygon('Neutral') Or  IsNamedPolygon('C106_2') Or  IsNamedPolygon('C106_2') Or  IsNamedPolygon('C106_2') Or  IsNamedPolygon('SWNODE') Or  IsNamedPolygon('Vbulk1') Or  IsNamedPolygon('Earth1') Or  IsNamedPolygon('Earth1') Or  IsNamedPolygon('Earth1') Or  IsNamedPolygon('Earth1') Or  IsNamedPolygon('Earth1') Or  IsNamedPolygon('Earth1') Or  IsNamedPolygon('ZCD') Or  IsNamedPolygon('VBB') Or  IsNamedPolygon('PGND') Or  IsNamedPolygon('D106_1') Or  IsNamedPolygon('PGND') Or  IsNamedPolygon('PGND') Or  IsNamedPolygon('D106_1') Or  IsNamedPolygon('Vbulk') Or  IsNamedPolygon('D106_1') Or  IsNamedPolygon('PGND') Or  IsNamedPolygon('VBB') Or  IsNamedPolygon('VBB') Or  IsNamedPolygon('PGND') Or  IsNamedPolygon('PGND') Or  IsNamedPolygon('PGND') Or  IsNamedPolygon('PGND') Or  IsNamedPolygon('PGND') Or  IsNamedPolygon('ZCD') Or  IsNamedPolygon('ZCD') Or  IsNamedPolygon('C412_2') Or  IsNamedPolygon('VBB') Or  IsNamedPolygon('PGND') Or  IsNamedPolygon('PGND') Or  IsNamedPolygon('PGND') Or  IsNamedPolygon('PGND') Or  IsNamedPolygon('PGND') Or  IsNamedPolygon('PGND') Or  IsNamedPolygon('PGND') Or  IsNamedPolygon('Vbulk') Or  IsNamedPolygon('D404_2') Or  IsNamedPolygon('PGND') Or  IsNamedPolygon('Iout_SNS') Or  IsNamedPolygon('54V2') Or  IsNamedPolygon('54V2') Or  IsNamedPolygon('54V2') Or  IsNamedPolygon('54V2') Or  IsNamedPolygon('VSR') Or  IsNamedPolygon('VSR') Or  IsNamedPolygon('Iout_SNS') Or  IsNamedPolygon('SGND') Or  IsNamedPolygon('SGND') Or  IsNamedPolygon('BOTTOM_LAYER_54V1_P154') Or  IsNamedPolygon('ZCD') Or  IsNamedPolygon('PGND')] p6: connectstyle=Direct reliefconductorwidth=10 reliefentries=4 polygonreliefangle="90 Angle" airgapwidth=10
PolygonConnect PolygonConnect_53 [All vs IsNamedPolygon('BOTTOM_LAYER_54V1_P350')] p7: connectstyle=Direct reliefconductorwidth=10 reliefentries=4 polygonreliefangle="90 Angle" airgapwidth=10
PolygonConnect PolygonConnect_52 [All vs IsNamedPolygon('TOP_LAYER_54V1_P046')] p8: connectstyle=Direct reliefconductorwidth=10 reliefentries=4 polygonreliefangle="90 Angle" airgapwidth=10
PolygonConnect PolygonConnect_51 [All vs IsNamedPolygon('SIGNAL_LAYER_1_VBULK1_P106')] p9: connectstyle=Direct reliefconductorwidth=10 reliefentries=4 polygonreliefangle="90 Angle" airgapwidth=10
PolygonConnect PolygonConnect_50 [All vs IsNamedPolygon('BOTTOM_LAYER_54V1_P128')] p10: connectstyle=Direct reliefconductorwidth=10 reliefentries=4 polygonreliefangle="90 Angle" airgapwidth=10
PolygonConnect PolygonConnect_49 [All vs IsNamedPolygon('BOTTOM_LAYER_54V1_P128')] p11: connectstyle=Direct reliefconductorwidth=10 reliefentries=4 polygonreliefangle="90 Angle" airgapwidth=10
PolygonConnect PolygonConnect_48 [All vs IsNamedPolygon('BOTTOM_LAYER_54V1_P128')] p12: connectstyle=Direct reliefconductorwidth=10 reliefentries=4 polygonreliefangle="90 Angle" airgapwidth=10
PolygonConnect PolygonConnect_47 [All vs IsNamedPolygon('BOTTOM_LAYER_54V1_P128')] p13: connectstyle=Direct reliefconductorwidth=10 reliefentries=4 polygonreliefangle="90 Angle" airgapwidth=10
PolygonConnect PolygonConnect_46 [All vs IsNamedPolygon('PGND') Or  IsNamedPolygon('T200_4') Or  IsNamedPolygon('VBB') Or  IsNamedPolygon('SWNODE3') Or  IsNamedPolygon('LEG4_LS_DRV') Or  IsNamedPolygon('Iout_SNS') Or  IsNamedPolygon('SWNODE3') Or  IsNamedPolygon('T200_6') Or  IsNamedPolygon('SGND') Or  IsNamedPolygon('SIGNAL_LAYER_1_VBULK1_P106') Or  IsNamedPolygon('LEG3_HS_DRV') Or  IsNamedPolygon('TOP_LAYER_12VS_P126') Or  IsNamedPolygon('LEG4_HS_DRV') Or  IsNamedPolygon('SWNODE3') Or  IsNamedPolygon('SGND') Or  IsNamedPolygon('BOTTOM_LAYER_54V1_P128') Or  IsNamedPolygon('SGND') Or  IsNamedPolygon('Line') Or  IsNamedPolygon('TOP_LAYER_IOUT_SNS_P092') Or  IsNamedPolygon('C108_1') Or  IsNamedPolygon('D403_2') Or  IsNamedPolygon('SWNODE') Or  IsNamedPolygon('SIGNAL_LAYER_2_VBB_P094') Or  IsNamedPolygon('Vbulk') Or  IsNamedPolygon('D404_2') Or  IsNamedPolygon('VSR') Or  IsNamedPolygon('C108_1') Or  IsNamedPolygon('C108_1') Or  IsNamedPolygon('5Vp') Or  IsNamedPolygon('C108_1') Or  IsNamedPolygon('PGND') Or  IsNamedPolygon('D400_2') Or  IsNamedPolygon('SWNODE3') Or  IsNamedPolygon('Line') Or  IsNamedPolygon('C108_1') Or  IsNamedPolygon('TOP_LAYER_VBULK_P104') Or  IsNamedPolygon('Vbulk1') Or  IsNamedPolygon('T200_6') Or  IsNamedPolygon('T200_6') Or  IsNamedPolygon('SWNODE4') Or  IsNamedPolygon('C108_1') Or  IsNamedPolygon('D403_2') Or  IsNamedPolygon('PGND') Or  IsNamedPolygon('T200_4') Or  IsNamedPolygon('Line') Or  IsNamedPolygon('5Vs') Or  IsNamedPolygon('12Vp') Or  IsNamedPolygon('C102_1') Or  IsNamedPolygon('SGND') Or  IsNamedPolygon('TOP_LAYER_54V2_P048') Or  IsNamedPolygon('TOP_LAYER_54V1_P046') Or  IsNamedPolygon('SWNODE4') Or  IsNamedPolygon('ZCD') Or  IsNamedPolygon('SWNODE3') Or  IsNamedPolygon('SWNODE3') Or  IsNamedPolygon('BOTTOM_LAYER_NETC106_2_P030') Or  IsNamedPolygon('TOP_LAYER_54V2_P048') Or  IsNamedPolygon('T200_4') Or  IsNamedPolygon('SWNODE4') Or  IsNamedPolygon('SWNODE4') Or  IsNamedPolygon('SGND') Or  IsNamedPolygon('SGND') Or  IsNamedPolygon('SGND') Or  IsNamedPolygon('SWNODE4') Or  IsNamedPolygon('VSR') Or  IsNamedPolygon('SWNODE3') Or  IsNamedPolygon('SGND') Or  IsNamedPolygon('SGND') Or  IsNamedPolygon('SGND') Or  IsNamedPolygon('SGND') Or  IsNamedPolygon('SGND') Or  IsNamedPolygon('SGND') Or  IsNamedPolygon('BOTTOM_LAYER_54V1_P128') Or  IsNamedPolygon('SGND') Or  IsNamedPolygon('VSR') Or  IsNamedPolygon('C102_1') Or  IsNamedPolygon('C102_1') Or  IsNamedPolygon('C102_1') Or  IsNamedPolygon('C102_1') Or  IsNamedPolygon('C102_1') Or  IsNamedPolygon('ZCD') Or  IsNamedPolygon('PGND') Or  IsNamedPolygon('PGND') Or  IsNamedPolygon('Vbulk1') Or  IsNamedPolygon('Vbulk') Or  IsNamedPolygon('Vbulk1') Or  IsNamedPolygon('Vbulk1') Or  IsNamedPolygon('ZCD') Or  IsNamedPolygon('Neutral') Or  IsNamedPolygon('Neutral') Or  IsNamedPolygon('C106_2') Or  IsNamedPolygon('C106_2') Or  IsNamedPolygon('C106_2') Or  IsNamedPolygon('SWNODE') Or  IsNamedPolygon('Vbulk1') Or  IsNamedPolygon('Earth1') Or  IsNamedPolygon('Earth1') Or  IsNamedPolygon('Earth1') Or  IsNamedPolygon('Earth1') Or  IsNamedPolygon('Earth1') Or  IsNamedPolygon('Earth1') Or  IsNamedPolygon('ZCD') Or  IsNamedPolygon('VBB') Or  IsNamedPolygon('PGND') Or  IsNamedPolygon('D106_1') Or  IsNamedPolygon('PGND') Or  IsNamedPolygon('PGND') Or  IsNamedPolygon('D106_1') Or  IsNamedPolygon('Vbulk') Or  IsNamedPolygon('D106_1') Or  IsNamedPolygon('PGND') Or  IsNamedPolygon('VBB') Or  IsNamedPolygon('VBB') Or  IsNamedPolygon('PGND') Or  IsNamedPolygon('PGND') Or  IsNamedPolygon('PGND') Or  IsNamedPolygon('PGND') Or  IsNamedPolygon('PGND') Or  IsNamedPolygon('ZCD') Or  IsNamedPolygon('ZCD') Or  IsNamedPolygon('C412_2') Or  IsNamedPolygon('VBB') Or  IsNamedPolygon('PGND') Or  IsNamedPolygon('PGND') Or  IsNamedPolygon('PGND') Or  IsNamedPolygon('PGND') Or  IsNamedPolygon('PGND') Or  IsNamedPolygon('PGND') Or  IsNamedPolygon('PGND') Or  IsNamedPolygon('Vbulk') Or  IsNamedPolygon('D404_2') Or  IsNamedPolygon('PGND') Or  IsNamedPolygon('Iout_SNS') Or  IsNamedPolygon('54V2')] p14: connectstyle=Direct reliefconductorwidth=10 reliefentries=4 polygonreliefangle="90 Angle" airgapwidth=10
PolygonConnect PolygonConnect_45 [All vs IsNamedPolygon('Vbulk1') Or  IsNamedPolygon('TOP_LAYER_VBULK_P104') Or  IsNamedPolygon('SIGNAL_LAYER_1_VBULK1_P106') Or  IsNamedPolygon('Iout_SNS') Or  IsNamedPolygon('SIGNAL_LAYER_2_VBB_P094') Or  IsNamedPolygon('Line') Or  IsNamedPolygon('T200_4') Or  IsNamedPolygon('ZCD') Or  IsNamedPolygon('C108_1') Or  IsNamedPolygon('PGND') Or  IsNamedPolygon('BOTTOM_LAYER_NETC106_2_P030') Or  IsNamedPolygon('5Vp') Or  IsNamedPolygon('C108_1') Or  IsNamedPolygon('Line') Or  IsNamedPolygon('C102_1') Or  IsNamedPolygon('T200_4') Or  IsNamedPolygon('12Vp') Or  IsNamedPolygon('D403_2') Or  IsNamedPolygon('T200_6') Or  IsNamedPolygon('TOP_LAYER_54V1_P046') Or  IsNamedPolygon('TOP_LAYER_54V2_P048') Or  IsNamedPolygon('C108_1') Or  IsNamedPolygon('C108_1') Or  IsNamedPolygon('SWNODE3') Or  IsNamedPolygon('TOP_LAYER_54V2_P048') Or  IsNamedPolygon('PGND') Or  IsNamedPolygon('D403_2') Or  IsNamedPolygon('C108_1') Or  IsNamedPolygon('C108_1') Or  IsNamedPolygon('T200_6') Or  IsNamedPolygon('SGND') Or  IsNamedPolygon('SWNODE') Or  IsNamedPolygon('SGND') Or  IsNamedPolygon('SWNODE3') Or  IsNamedPolygon('BOTTOM_LAYER_54V1_P128') Or  IsNamedPolygon('C102_1') Or  IsNamedPolygon('SWNODE4') Or  IsNamedPolygon('C102_1') Or  IsNamedPolygon('SGND') Or  IsNamedPolygon('C102_1') Or  IsNamedPolygon('SGND') Or  IsNamedPolygon('VSR') Or  IsNamedPolygon('SGND') Or  IsNamedPolygon('SGND') Or  IsNamedPolygon('VSR') Or  IsNamedPolygon('SGND') Or  IsNamedPolygon('SWNODE4') Or  IsNamedPolygon('SGND') Or  IsNamedPolygon('SGND') Or  IsNamedPolygon('Vbulk1') Or  IsNamedPolygon('SGND') Or  IsNamedPolygon('PGND') Or  IsNamedPolygon('SGND') Or  IsNamedPolygon('PGND') Or  IsNamedPolygon('SWNODE3') Or  IsNamedPolygon('ZCD') Or  IsNamedPolygon('VSR') Or  IsNamedPolygon('C102_1') Or  IsNamedPolygon('SWNODE4') Or  IsNamedPolygon('C102_1') Or  IsNamedPolygon('SWNODE4') Or  IsNamedPolygon('SWNODE3') Or  IsNamedPolygon('PGND') Or  IsNamedPolygon('SGND') Or  IsNamedPolygon('D400_2') Or  IsNamedPolygon('SGND') Or  IsNamedPolygon('5Vs') Or  IsNamedPolygon('VBB') Or  IsNamedPolygon('T200_4') Or  IsNamedPolygon('T200_6') Or  IsNamedPolygon('SWNODE4') Or  IsNamedPolygon('LEG4_HS_DRV') Or  IsNamedPolygon('LEG4_LS_DRV') Or  IsNamedPolygon('LEG3_HS_DRV') Or  IsNamedPolygon('BOTTOM_LAYER_54V1_P128') Or  IsNamedPolygon('TOP_LAYER_12VS_P126') Or  IsNamedPolygon('Iout_SNS') Or  IsNamedPolygon('SWNODE3') Or  IsNamedPolygon('SWNODE3') Or  IsNamedPolygon('SWNODE3') Or  IsNamedPolygon('VBB') Or  IsNamedPolygon('Line') Or  IsNamedPolygon('D404_2') Or  IsNamedPolygon('SGND') Or  IsNamedPolygon('VBB') Or  IsNamedPolygon('VBB') Or  IsNamedPolygon('PGND') Or  IsNamedPolygon('PGND') Or  IsNamedPolygon('PGND') Or  IsNamedPolygon('PGND') Or  IsNamedPolygon('PGND') Or  IsNamedPolygon('ZCD') Or  IsNamedPolygon('ZCD') Or  IsNamedPolygon('C412_2') Or  IsNamedPolygon('VBB') Or  IsNamedPolygon('PGND') Or  IsNamedPolygon('PGND') Or  IsNamedPolygon('PGND') Or  IsNamedPolygon('PGND') Or  IsNamedPolygon('PGND') Or  IsNamedPolygon('PGND') Or  IsNamedPolygon('PGND') Or  IsNamedPolygon('VBB') Or  IsNamedPolygon('D404_2') Or  IsNamedPolygon('VBB') Or  IsNamedPolygon('Vbulk1') Or  IsNamedPolygon('Vbulk1') Or  IsNamedPolygon('ZCD') Or  IsNamedPolygon('Neutral') Or  IsNamedPolygon('Neutral') Or  IsNamedPolygon('C106_2') Or  IsNamedPolygon('C106_2') Or  IsNamedPolygon('C106_2') Or  IsNamedPolygon('SWNODE') Or  IsNamedPolygon('Vbulk1') Or  IsNamedPolygon('Earth1') Or  IsNamedPolygon('Earth1') Or  IsNamedPolygon('Earth1') Or  IsNamedPolygon('Earth1') Or  IsNamedPolygon('Earth1') Or  IsNamedPolygon('Earth1') Or  IsNamedPolygon('ZCD') Or  IsNamedPolygon('VBB') Or  IsNamedPolygon('PGND') Or  IsNamedPolygon('D106_1') Or  IsNamedPolygon('PGND') Or  IsNamedPolygon('PGND') Or  IsNamedPolygon('D106_1') Or  IsNamedPolygon('VBB') Or  IsNamedPolygon('D106_1') Or  IsNamedPolygon('PGND')] p15: connectstyle=Direct reliefconductorwidth=10 reliefentries=4 polygonreliefangle="90 Angle" airgapwidth=10
PolygonConnect PolygonConnect_44 [All vs IsNamedPolygon('Earth1') Or  IsNamedPolygon('Vbulk1') Or  IsNamedPolygon('Vbulk1') Or  IsNamedPolygon('VBB') Or  IsNamedPolygon('Vbulk1') Or  IsNamedPolygon('ZCD') Or  IsNamedPolygon('VBB') Or  IsNamedPolygon('PGND') Or  IsNamedPolygon('C412_2') Or  IsNamedPolygon('ZCD') Or  IsNamedPolygon('D106_1') Or  IsNamedPolygon('D106_1') Or  IsNamedPolygon('ZCD') Or  IsNamedPolygon('PGND') Or  IsNamedPolygon('PGND') Or  IsNamedPolygon('ZCD') Or  IsNamedPolygon('VBB') Or  IsNamedPolygon('PGND') Or  IsNamedPolygon('VBB') Or  IsNamedPolygon('PGND') Or  IsNamedPolygon('D106_1') Or  IsNamedPolygon('PGND') Or  IsNamedPolygon('PGND') Or  IsNamedPolygon('PGND') Or  IsNamedPolygon('VBB') Or  IsNamedPolygon('PGND') Or  IsNamedPolygon('PGND') Or  IsNamedPolygon('C102_1') Or  IsNamedPolygon('ZCD') Or  IsNamedPolygon('C102_1') Or  IsNamedPolygon('C102_1') Or  IsNamedPolygon('C102_1') Or  IsNamedPolygon('PGND') Or  IsNamedPolygon('C102_1') Or  IsNamedPolygon('Line') Or  IsNamedPolygon('T200_4') Or  IsNamedPolygon('T200_4') Or  IsNamedPolygon('SIGNAL_LAYER_1_VBULK1_P106') Or  IsNamedPolygon('TOP_LAYER_VBULK_P104') Or  IsNamedPolygon('T200_4') Or  IsNamedPolygon('SGND') Or  IsNamedPolygon('T200_6') Or  IsNamedPolygon('C108_1') Or  IsNamedPolygon('SWNODE3') Or  IsNamedPolygon('SWNODE') Or  IsNamedPolygon('SWNODE3') Or  IsNamedPolygon('LEG3_HS_DRV') Or  IsNamedPolygon('BOTTOM_LAYER_NETC106_2_P030') Or  IsNamedPolygon('C102_1') Or  IsNamedPolygon('SWNODE4') Or  IsNamedPolygon('SIGNAL_LAYER_2_VBB_P094') Or  IsNamedPolygon('SGND') Or  IsNamedPolygon('VSR') Or  IsNamedPolygon('C108_1') Or  IsNamedPolygon('BOTTOM_LAYER_54V1_P128') Or  IsNamedPolygon('TOP_LAYER_54V2_P048') Or  IsNamedPolygon('TOP_LAYER_54V1_P046') Or  IsNamedPolygon('C108_1') Or  IsNamedPolygon('D403_2') Or  IsNamedPolygon('ZCD') Or  IsNamedPolygon('PGND') Or  IsNamedPolygon('SWNODE3') Or  IsNamedPolygon('Line') Or  IsNamedPolygon('D400_2') Or  IsNamedPolygon('SGND') Or  IsNamedPolygon('PGND') Or  IsNamedPolygon('SGND') Or  IsNamedPolygon('LEG4_HS_DRV') Or  IsNamedPolygon('SWNODE3') Or  IsNamedPolygon('5Vs') Or  IsNamedPolygon('SWNODE4') Or  IsNamedPolygon('SGND') Or  IsNamedPolygon('SGND') Or  IsNamedPolygon('C108_1') Or  IsNamedPolygon('5Vp') Or  IsNamedPolygon('12Vp') Or  IsNamedPolygon('Iout_SNS') Or  IsNamedPolygon('D404_2') Or  IsNamedPolygon('SGND') Or  IsNamedPolygon('T200_6') Or  IsNamedPolygon('TOP_LAYER_54V2_P048') Or  IsNamedPolygon('SGND') Or  IsNamedPolygon('SWNODE3') Or  IsNamedPolygon('SWNODE4') Or  IsNamedPolygon('Iout_SNS') Or  IsNamedPolygon('C108_1') Or  IsNamedPolygon('BOTTOM_LAYER_54V1_P128') Or  IsNamedPolygon('SWNODE3') Or  IsNamedPolygon('LEG4_LS_DRV') Or  IsNamedPolygon('SGND') Or  IsNamedPolygon('SWNODE4') Or  IsNamedPolygon('T200_6') Or  IsNamedPolygon('TOP_LAYER_12VS_P126') Or  IsNamedPolygon('Line') Or  IsNamedPolygon('Vbulk1') Or  IsNamedPolygon('SWNODE3') Or  IsNamedPolygon('SGND') Or  IsNamedPolygon('VBB') Or  IsNamedPolygon('SGND') Or  IsNamedPolygon('SGND') Or  IsNamedPolygon('SWNODE4') Or  IsNamedPolygon('PGND') Or  IsNamedPolygon('D403_2') Or  IsNamedPolygon('VSR') Or  IsNamedPolygon('SGND') Or  IsNamedPolygon('SGND') Or  IsNamedPolygon('VBB') Or  IsNamedPolygon('C108_1') Or  IsNamedPolygon('Earth1') Or  IsNamedPolygon('Earth1') Or  IsNamedPolygon('VSR') Or  IsNamedPolygon('C106_2') Or  IsNamedPolygon('Vbulk1') Or  IsNamedPolygon('C106_2') Or  IsNamedPolygon('C106_2') Or  IsNamedPolygon('Earth1') Or  IsNamedPolygon('SWNODE') Or  IsNamedPolygon('Neutral') Or  IsNamedPolygon('Earth1') Or  IsNamedPolygon('Earth1') Or  IsNamedPolygon('Neutral')] p16: connectstyle=Direct reliefconductorwidth=10 reliefentries=4 polygonreliefangle="90 Angle" airgapwidth=10
PolygonConnect PolygonConnect_43 [All vs IsNamedPolygon('SWNODE') Or  IsNamedPolygon('D403_2') Or  IsNamedPolygon('D403_2') Or  IsNamedPolygon('PGND') Or  IsNamedPolygon('BOTTOM_LAYER_NETC106_2_P030') Or  IsNamedPolygon('C102_1') Or  IsNamedPolygon('SGND') Or  IsNamedPolygon('TOP_LAYER_54V1_P046') Or  IsNamedPolygon('TOP_LAYER_54V2_P048') Or  IsNamedPolygon('TOP_LAYER_54V2_P048') Or  IsNamedPolygon('C108_1') Or  IsNamedPolygon('C108_1') Or  IsNamedPolygon('C108_1') Or  IsNamedPolygon('C108_1') Or  IsNamedPolygon('C108_1') Or  IsNamedPolygon('C108_1') Or  IsNamedPolygon('PGND') Or  IsNamedPolygon('ZCD') Or  IsNamedPolygon('Line') Or  IsNamedPolygon('5Vp') Or  IsNamedPolygon('12Vp') Or  IsNamedPolygon('T200_4') Or  IsNamedPolygon('T200_6') Or  IsNamedPolygon('SWNODE3') Or  IsNamedPolygon('T200_4') Or  IsNamedPolygon('T200_6') Or  IsNamedPolygon('SWNODE4') Or  IsNamedPolygon('VSR') Or  IsNamedPolygon('Iout_SNS') Or  IsNamedPolygon('SIGNAL_LAYER_2_VBB_P094') Or  IsNamedPolygon('Vbulk1') Or  IsNamedPolygon('TOP_LAYER_VBULK_P104') Or  IsNamedPolygon('SIGNAL_LAYER_1_VBULK1_P106') Or  IsNamedPolygon('Line') Or  IsNamedPolygon('Line') Or  IsNamedPolygon('D404_2') Or  IsNamedPolygon('VBB') Or  IsNamedPolygon('D400_2') Or  IsNamedPolygon('SGND') Or  IsNamedPolygon('PGND') Or  IsNamedPolygon('TOP_LAYER_12VS_P126') Or  IsNamedPolygon('BOTTOM_LAYER_54V1_P128') Or  IsNamedPolygon('LEG3_HS_DRV') Or  IsNamedPolygon('LEG4_LS_DRV') Or  IsNamedPolygon('LEG4_HS_DRV') Or  IsNamedPolygon('SWNODE4') Or  IsNamedPolygon('SWNODE3') Or  IsNamedPolygon('T200_6') Or  IsNamedPolygon('T200_4') Or  IsNamedPolygon('VBB') Or  IsNamedPolygon('5Vs') Or  IsNamedPolygon('SGND') Or  IsNamedPolygon('Iout_SNS') Or  IsNamedPolygon('SGND') Or  IsNamedPolygon('SWNODE3') Or  IsNamedPolygon('SWNODE3') Or  IsNamedPolygon('SWNODE3') Or  IsNamedPolygon('SWNODE3') Or  IsNamedPolygon('SGND') Or  IsNamedPolygon('SGND') Or  IsNamedPolygon('SGND') Or  IsNamedPolygon('SWNODE4') Or  IsNamedPolygon('SWNODE4') Or  IsNamedPolygon('SWNODE4') Or  IsNamedPolygon('VSR') Or  IsNamedPolygon('SWNODE3') Or  IsNamedPolygon('SGND') Or  IsNamedPolygon('SGND') Or  IsNamedPolygon('SGND') Or  IsNamedPolygon('SGND') Or  IsNamedPolygon('SGND') Or  IsNamedPolygon('SGND') Or  IsNamedPolygon('BOTTOM_LAYER_54V1_P128') Or  IsNamedPolygon('SGND') Or  IsNamedPolygon('VSR') Or  IsNamedPolygon('C102_1') Or  IsNamedPolygon('C102_1') Or  IsNamedPolygon('C102_1') Or  IsNamedPolygon('C102_1') Or  IsNamedPolygon('C102_1') Or  IsNamedPolygon('ZCD') Or  IsNamedPolygon('PGND') Or  IsNamedPolygon('PGND') Or  IsNamedPolygon('Vbulk1') Or  IsNamedPolygon('VBB') Or  IsNamedPolygon('Vbulk1') Or  IsNamedPolygon('Vbulk1') Or  IsNamedPolygon('ZCD') Or  IsNamedPolygon('Neutral') Or  IsNamedPolygon('Neutral') Or  IsNamedPolygon('C106_2') Or  IsNamedPolygon('C106_2') Or  IsNamedPolygon('C106_2') Or  IsNamedPolygon('SWNODE') Or  IsNamedPolygon('Vbulk1') Or  IsNamedPolygon('Earth1') Or  IsNamedPolygon('Earth1') Or  IsNamedPolygon('Earth1') Or  IsNamedPolygon('Earth1') Or  IsNamedPolygon('Earth1') Or  IsNamedPolygon('Earth1') Or  IsNamedPolygon('ZCD') Or  IsNamedPolygon('VBB') Or  IsNamedPolygon('PGND') Or  IsNamedPolygon('D106_1') Or  IsNamedPolygon('PGND') Or  IsNamedPolygon('PGND') Or  IsNamedPolygon('D106_1') Or  IsNamedPolygon('VBB') Or  IsNamedPolygon('D106_1') Or  IsNamedPolygon('PGND') Or  IsNamedPolygon('VBB') Or  IsNamedPolygon('VBB') Or  IsNamedPolygon('PGND') Or  IsNamedPolygon('PGND') Or  IsNamedPolygon('PGND') Or  IsNamedPolygon('PGND') Or  IsNamedPolygon('PGND')] p17: connectstyle=Direct reliefconductorwidth=10 reliefentries=4 polygonreliefangle="90 Angle" airgapwidth=10
PolygonConnect PolygonConnect_42 [All vs IsNamedPolygon('Neutral') Or  IsNamedPolygon('Earth1') Or  IsNamedPolygon('Earth1') Or  IsNamedPolygon('D404_2') Or  IsNamedPolygon('Line') Or  IsNamedPolygon('SIGNAL_LAYER_1_VBULK1_P106') Or  IsNamedPolygon('Line') Or  IsNamedPolygon('C102_1') Or  IsNamedPolygon('SWNODE3') Or  IsNamedPolygon('SWNODE3') Or  IsNamedPolygon('SWNODE') Or  IsNamedPolygon('5Vp') Or  IsNamedPolygon('T200_6') Or  IsNamedPolygon('SWNODE3') Or  IsNamedPolygon('SGND') Or  IsNamedPolygon('SWNODE3') Or  IsNamedPolygon('VSR') Or  IsNamedPolygon('C108_1') Or  IsNamedPolygon('SWNODE3') Or  IsNamedPolygon('TOP_LAYER_12VS_P126') Or  IsNamedPolygon('SGND') Or  IsNamedPolygon('SGND') Or  IsNamedPolygon('SGND') Or  IsNamedPolygon('T200_6') Or  IsNamedPolygon('SWNODE4') Or  IsNamedPolygon('C108_1') Or  IsNamedPolygon('C106_2') Or  IsNamedPolygon('SGND') Or  IsNamedPolygon('Neutral') Or  IsNamedPolygon('SIGNAL_LAYER_2_VBB_P094') Or  IsNamedPolygon('Vbulk1') Or  IsNamedPolygon('SGND') Or  IsNamedPolygon('SGND') Or  IsNamedPolygon('TOP_LAYER_54V1_P046') Or  IsNamedPolygon('TOP_LAYER_54V2_P048') Or  IsNamedPolygon('TOP_LAYER_54V2_P048') Or  IsNamedPolygon('C102_1') Or  IsNamedPolygon('SGND') Or  IsNamedPolygon('T200_4') Or  IsNamedPolygon('12Vp') Or  IsNamedPolygon('SGND') Or  IsNamedPolygon('D400_2') Or  IsNamedPolygon('LEG3_HS_DRV') Or  IsNamedPolygon('LEG4_LS_DRV') Or  IsNamedPolygon('T200_4') Or  IsNamedPolygon('BOTTOM_LAYER_54V1_P128') Or  IsNamedPolygon('SGND') Or  IsNamedPolygon('VBB') Or  IsNamedPolygon('SWNODE4') Or  IsNamedPolygon('SWNODE4') Or  IsNamedPolygon('SWNODE4') Or  IsNamedPolygon('VSR') Or  IsNamedPolygon('Iout_SNS') Or  IsNamedPolygon('VBB') Or  IsNamedPolygon('PGND') Or  IsNamedPolygon('Line') Or  IsNamedPolygon('ZCD') Or  IsNamedPolygon('D403_2') Or  IsNamedPolygon('SWNODE3') Or  IsNamedPolygon('Vbulk1') Or  IsNamedPolygon('ZCD') Or  IsNamedPolygon('LEG4_HS_DRV') Or  IsNamedPolygon('BOTTOM_LAYER_54V1_P128') Or  IsNamedPolygon('VBB') Or  IsNamedPolygon('PGND') Or  IsNamedPolygon('ZCD') Or  IsNamedPolygon('ZCD') Or  IsNamedPolygon('Earth1') Or  IsNamedPolygon('VBB') Or  IsNamedPolygon('PGND') Or  IsNamedPolygon('PGND') Or  IsNamedPolygon('Vbulk1') Or  IsNamedPolygon('SWNODE') Or  IsNamedPolygon('C106_2') Or  IsNamedPolygon('C106_2') Or  IsNamedPolygon('C108_1') Or  IsNamedPolygon('SWNODE3') Or  IsNamedPolygon('SWNODE4') Or  IsNamedPolygon('Vbulk1') Or  IsNamedPolygon('SGND') Or  IsNamedPolygon('C102_1') Or  IsNamedPolygon('BOTTOM_LAYER_NETC106_2_P030') Or  IsNamedPolygon('Earth1') Or  IsNamedPolygon('Earth1') Or  IsNamedPolygon('Vbulk1') Or  IsNamedPolygon('Earth1') Or  IsNamedPolygon('T200_6') Or  IsNamedPolygon('T200_4') Or  IsNamedPolygon('C102_1') Or  IsNamedPolygon('C102_1') Or  IsNamedPolygon('C102_1') Or  IsNamedPolygon('VBB') Or  IsNamedPolygon('5Vs') Or  IsNamedPolygon('SGND') Or  IsNamedPolygon('Iout_SNS') Or  IsNamedPolygon('C108_1') Or  IsNamedPolygon('C108_1') Or  IsNamedPolygon('C108_1') Or  IsNamedPolygon('PGND') Or  IsNamedPolygon('D403_2') Or  IsNamedPolygon('PGND') Or  IsNamedPolygon('SGND') Or  IsNamedPolygon('SGND') Or  IsNamedPolygon('VSR')] p18: connectstyle=Direct reliefconductorwidth=10 reliefentries=4 polygonreliefangle="90 Angle" airgapwidth=10
PolygonConnect PolygonConnect_41 [All vs IsNamedPolygon('VBB') Or  IsNamedPolygon('SWNODE3') Or  IsNamedPolygon('T200_4') Or  IsNamedPolygon('Earth1') Or  IsNamedPolygon('BOTTOM_LAYER_54V1_P128') Or  IsNamedPolygon('SGND') Or  IsNamedPolygon('TOP_LAYER_12VS_P126') Or  IsNamedPolygon('C102_1') Or  IsNamedPolygon('VSR') Or  IsNamedPolygon('Earth1') Or  IsNamedPolygon('Neutral') Or  IsNamedPolygon('Vbulk1') Or  IsNamedPolygon('SWNODE4') Or  IsNamedPolygon('C106_2') Or  IsNamedPolygon('PGND') Or  IsNamedPolygon('SGND') Or  IsNamedPolygon('VBB') Or  IsNamedPolygon('PGND') Or  IsNamedPolygon('LEG4_LS_DRV') Or  IsNamedPolygon('C102_1') Or  IsNamedPolygon('SWNODE4') Or  IsNamedPolygon('C106_2') Or  IsNamedPolygon('Vbulk1') Or  IsNamedPolygon('C102_1') Or  IsNamedPolygon('BOTTOM_LAYER_54V1_P128') Or  IsNamedPolygon('LEG3_HS_DRV') Or  IsNamedPolygon('SGND') Or  IsNamedPolygon('SGND') Or  IsNamedPolygon('Earth1') Or  IsNamedPolygon('SGND') Or  IsNamedPolygon('SGND') Or  IsNamedPolygon('5Vs') Or  IsNamedPolygon('LEG4_HS_DRV') Or  IsNamedPolygon('Earth1') Or  IsNamedPolygon('SGND') Or  IsNamedPolygon('SWNODE3') Or  IsNamedPolygon('Iout_SNS') Or  IsNamedPolygon('ZCD') Or  IsNamedPolygon('Earth1') Or  IsNamedPolygon('VSR') Or  IsNamedPolygon('C102_1') Or  IsNamedPolygon('C102_1') Or  IsNamedPolygon('Vbulk1') Or  IsNamedPolygon('C106_2') Or  IsNamedPolygon('ZCD') Or  IsNamedPolygon('SWNODE3') Or  IsNamedPolygon('SWNODE3') Or  IsNamedPolygon('Vbulk1') Or  IsNamedPolygon('SWNODE4') Or  IsNamedPolygon('Neutral') Or  IsNamedPolygon('SWNODE3') Or  IsNamedPolygon('SWNODE4') Or  IsNamedPolygon('Earth1') Or  IsNamedPolygon('D400_2') Or  IsNamedPolygon('SGND') Or  IsNamedPolygon('SGND') Or  IsNamedPolygon('SGND') Or  IsNamedPolygon('SWNODE') Or  IsNamedPolygon('VSR') Or  IsNamedPolygon('SGND') Or  IsNamedPolygon('SIGNAL_LAYER_1_VBULK1_P106') Or  IsNamedPolygon('SGND') Or  IsNamedPolygon('T200_6') Or  IsNamedPolygon('SWNODE4') Or  IsNamedPolygon('VBB') Or  IsNamedPolygon('T200_6') Or  IsNamedPolygon('Line') Or  IsNamedPolygon('Iout_SNS') Or  IsNamedPolygon('Vbulk1') Or  IsNamedPolygon('VBB') Or  IsNamedPolygon('SIGNAL_LAYER_2_VBB_P094') Or  IsNamedPolygon('SGND') Or  IsNamedPolygon('D404_2') Or  IsNamedPolygon('SWNODE3') Or  IsNamedPolygon('Line') Or  IsNamedPolygon('PGND') Or  IsNamedPolygon('TOP_LAYER_54V2_P048') Or  IsNamedPolygon('TOP_LAYER_54V1_P046') Or  IsNamedPolygon('TOP_LAYER_54V2_P048') Or  IsNamedPolygon('C108_1') Or  IsNamedPolygon('BOTTOM_LAYER_NETC106_2_P030') Or  IsNamedPolygon('D403_2') Or  IsNamedPolygon('T200_4') Or  IsNamedPolygon('Line') Or  IsNamedPolygon('PGND') Or  IsNamedPolygon('SWNODE3') Or  IsNamedPolygon('ZCD') Or  IsNamedPolygon('SWNODE') Or  IsNamedPolygon('D403_2') Or  IsNamedPolygon('C108_1') Or  IsNamedPolygon('C102_1') Or  IsNamedPolygon('C108_1') Or  IsNamedPolygon('PGND') Or  IsNamedPolygon('C108_1') Or  IsNamedPolygon('C108_1') Or  IsNamedPolygon('5Vp') Or  IsNamedPolygon('T200_4') Or  IsNamedPolygon('12Vp') Or  IsNamedPolygon('T200_6') Or  IsNamedPolygon('C108_1') Or  IsNamedPolygon('SGND')] p19: connectstyle=Direct reliefconductorwidth=10 reliefentries=4 polygonreliefangle="90 Angle" airgapwidth=10
PolygonConnect PolygonConnect_40 [All vs IsNamedPolygon('Neutral')] p20: connectstyle=Direct reliefconductorwidth=10 reliefentries=4 polygonreliefangle="90 Angle" airgapwidth=10
PolygonConnect PolygonConnect_39 [All vs IsNamedPolygon('12Vp')] p21: connectstyle=Direct reliefconductorwidth=10 reliefentries=4 polygonreliefangle="90 Angle" airgapwidth=10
